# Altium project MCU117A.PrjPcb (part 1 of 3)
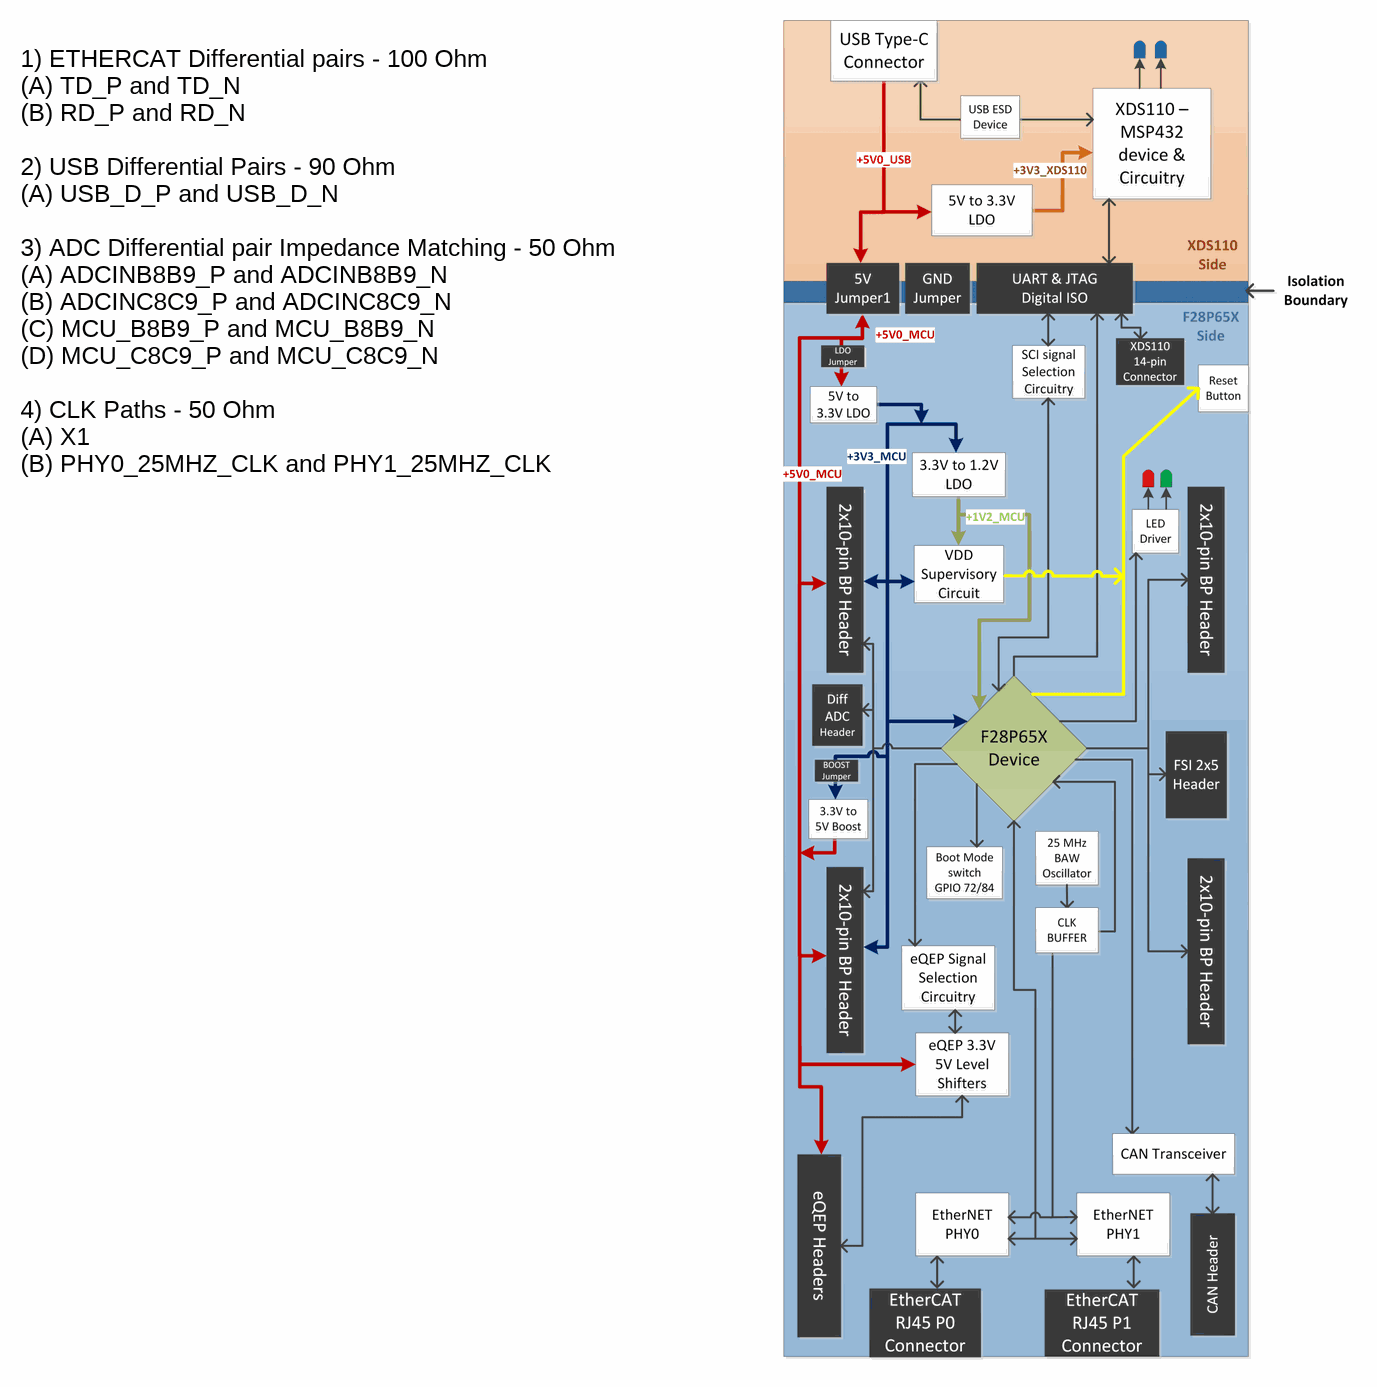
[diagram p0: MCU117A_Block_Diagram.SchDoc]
CopyrightYear: 2023; DrawnBy: Peter Luong; EVM_orderable: LAUNCHXL-F28P65X; PCB_Layout: a0488298; PCB_Rev: A; PRJ_Customer: Public Release; PRJ_Engineer: Peter Luong; PRJ_Number: MCU117; PRJ_Title: LAUNCHXL-F28P65X; SCH_Rev: A; TechSupport: http://www.ti.com/support; TID: N/A
9 sheets, 425 parts. Net scope: global (net labels, ports and power ports of the same name join across sheets).
Board file: MCU117A.PcbDoc
Sheets:
  MCU117A_Block_Diagram.SchDoc
  MCU117A_Connectors.SchDoc
  MCU117A_AltRouting_Misc.SchDoc
  MCU117A_F28P65X_Device.SchDoc
  MCU117A_ADC.SchDoc
  MCU117A_EtherCAT.SchDoc
  MCU117A_USB_and_Power.SchDoc
  MCU117A_XDS110_MCU.SchDoc
  MCU117A_Hardware.SchDoc

## Sheet MCU117A_Block_Diagram.SchDoc
size 431 x 279 mm; Date: Not shown in title block; ApprovedBy: Not shown in title block; CheckedBy: Not shown in title block; Author: Not shown in title block; CompanyName: Not shown in title block; Engineer: Not shown in title block; Organization: Not shown in title block; Address1: Not shown in title block; Address2: Not shown in title block; Address3: Not shown in title block; Address4: Not shown in title block; DocumentNumber: 1; Revision: Use project parameter SCH_Rev; SheetNumber: 1; SheetTotal: 9; PageSetup: Record=PageOptions¦CenterHorizontal=True¦CenterVertical=True¦PrintScale=1.00¦XCorrection=1.00¦YCorrection=1.00¦PrintKind=0¦BorderSize=5000000¦LeftOffset=0¦BottomOffset=0¦Orientation=2¦PaperLength=1000¦PaperWidth=1000¦Scale=100¦PaperSource=15¦PrintQuality=600¦MediaType=1¦DitherType=10¦PaperKind=Letter¦PrintScaleMode=1

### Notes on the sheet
- 1) ETHERCAT Differential pairs - 100 Ohm
  (A) TD_P and TD_N
  (B) RD_P and RD_N
  2) USB Differential Pairs - 90 Ohm
  (A) USB_D_P and USB_D_N
  3) ADC Differential pair Impedance Matching - 50 Ohm
  (A) ADCINB8B9_P and ADCINB8B9_N
  (B) ADCINC8C9_P and ADCINC8C9_N
  (C) MCU_B8B9_P and MCU_B8B9_N
  (D) MCU_C8C9_P and MCU_C8C9_N
  4) CLK Paths - 50 Ohm
  (A) X1
  (B) PHY0_25MHZ_CLK and PHY1_25MHZ_CLK

## Sheet MCU117A_Connectors.SchDoc
size 431 x 279 mm; Date: Not shown in title block; ApprovedBy: Not shown in title block; CheckedBy: Not shown in title block; Author: Not shown in title block; CompanyName: Not shown in title block; Engineer: Not shown in title block; Organization: Not shown in title block; Address1: Not shown in title block; Address2: Not shown in title block; Address3: Not shown in title block; Address4: Not shown in title block; DocumentNumber: 2; Revision: Use project parameter SCH_Rev; SheetNumber: 2; SheetTotal: 9; PageSetup: Record=PageOptions¦CenterHorizontal=True¦CenterVertical=True¦PrintScale=1.00¦XCorrection=1.00¦YCorrection=1.00¦PrintKind=0¦BorderSize=5000000¦LeftOffset=0¦BottomOffset=0¦Orientation=2¦PaperLength=1000¦PaperWidth=1000¦Scale=100¦PaperSource=15¦PrintQuality=600¦MediaType=1¦DitherType=10¦PaperKind=Letter¦PrintScaleMode=1
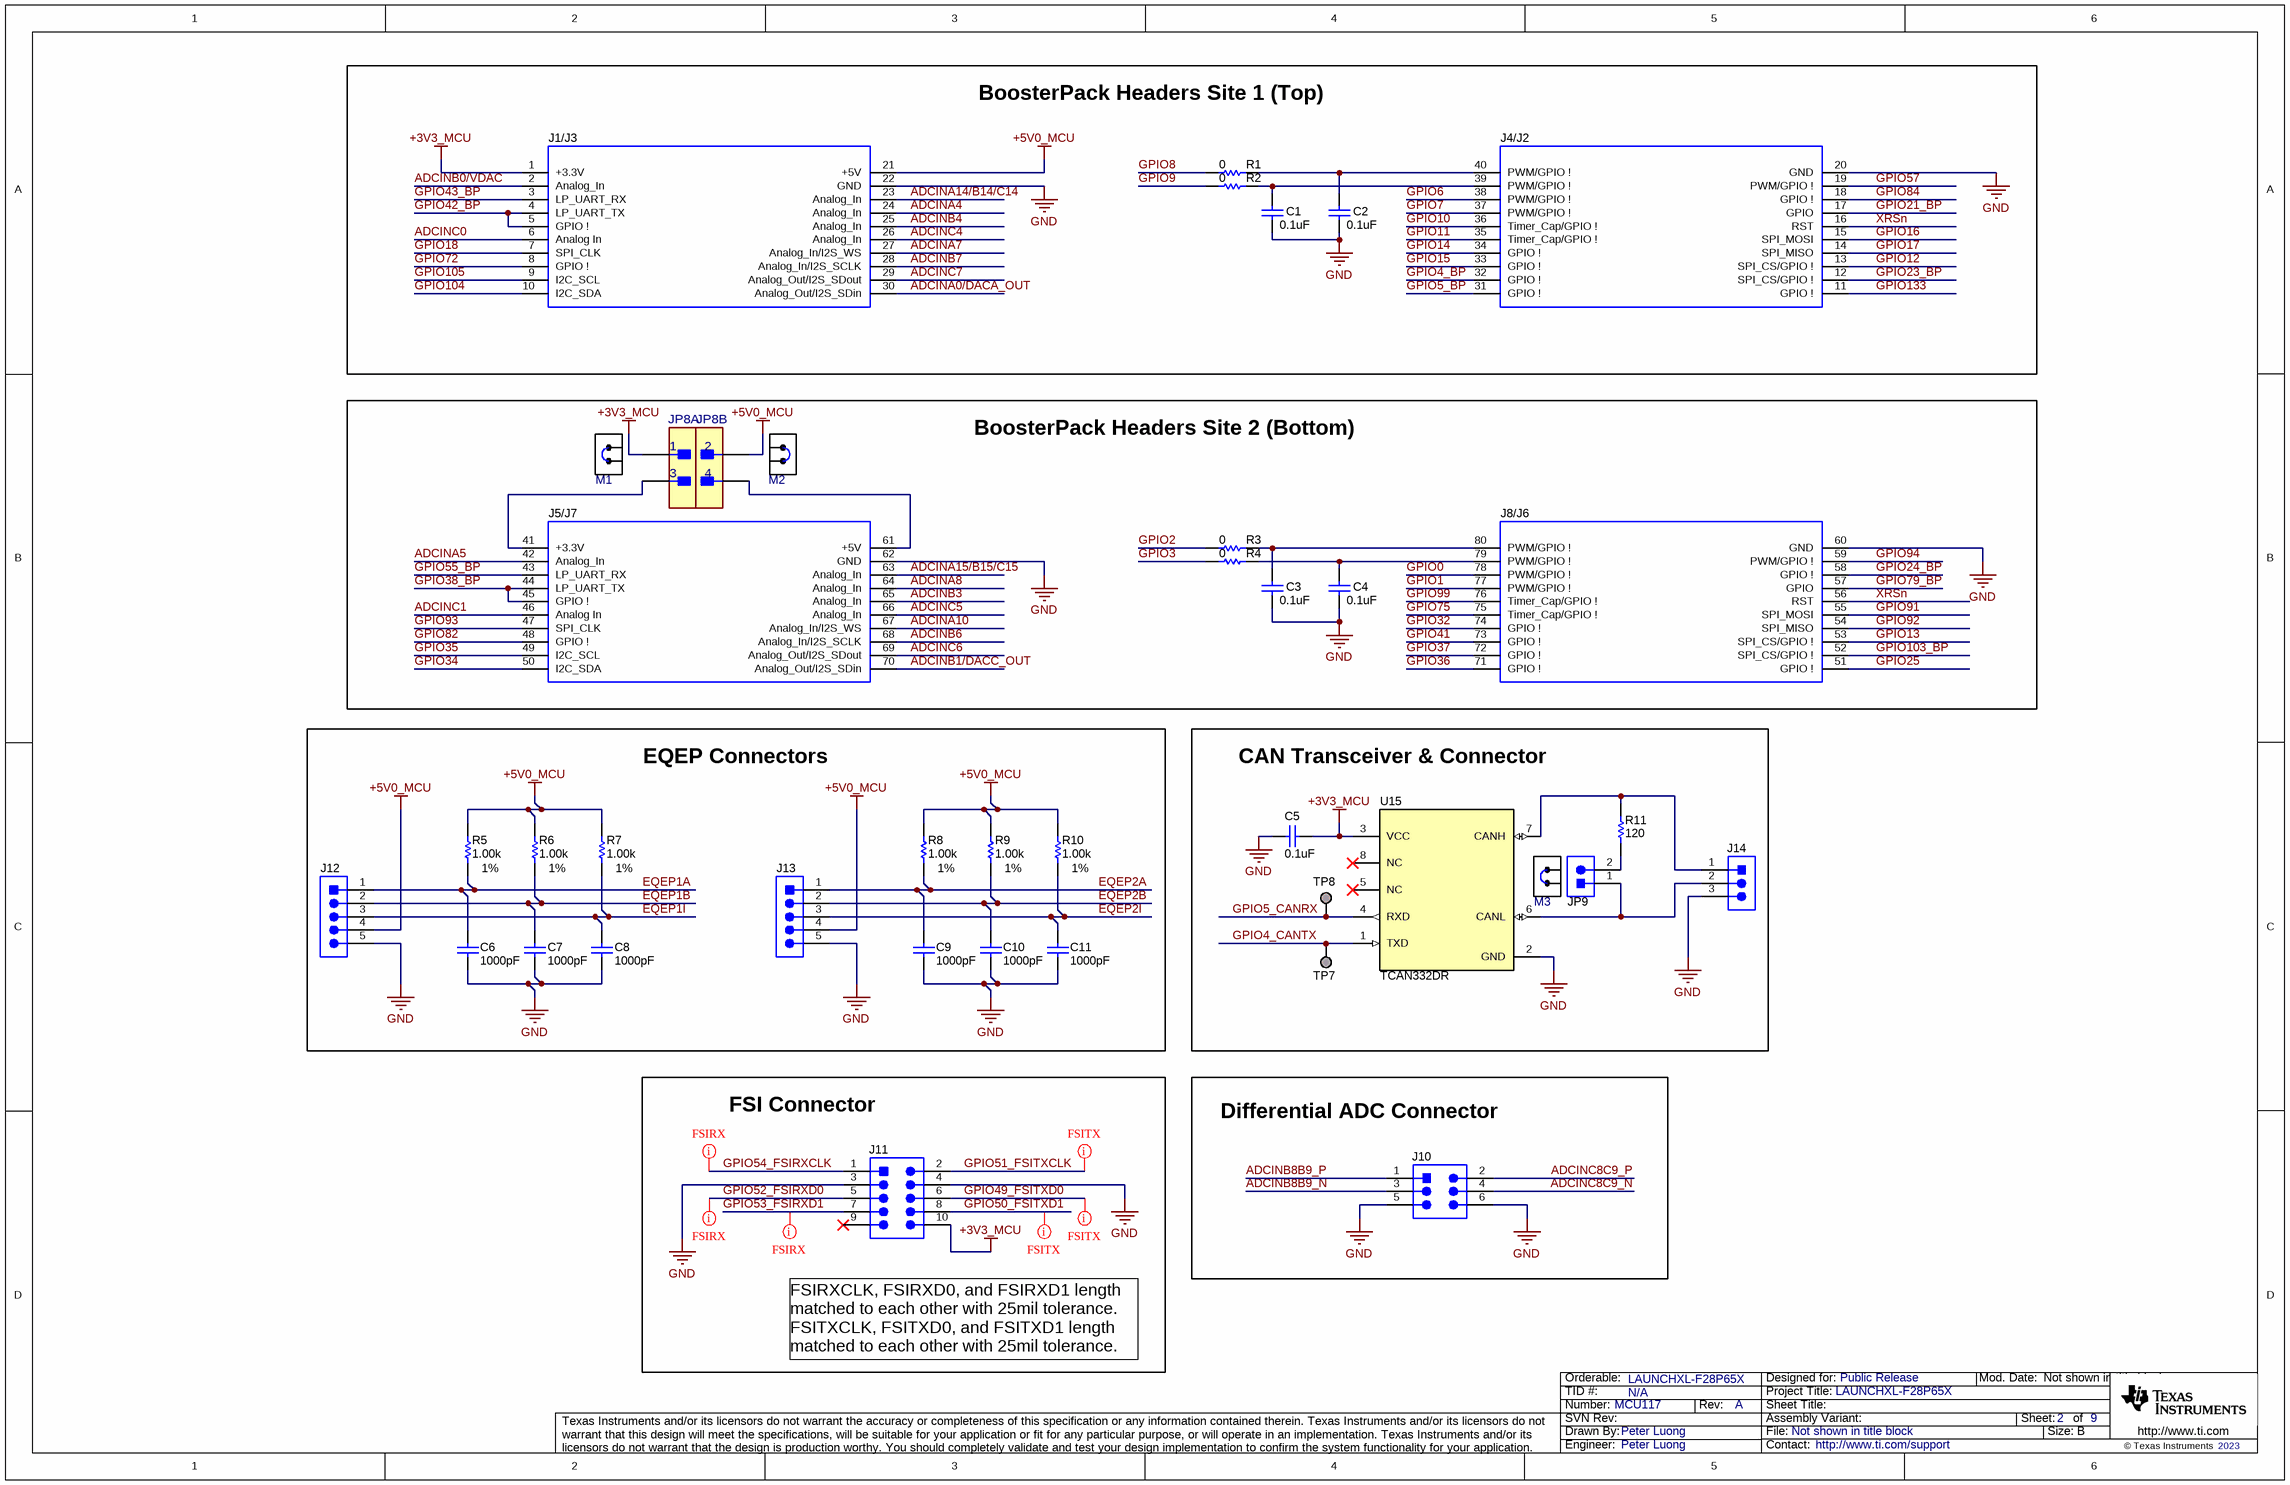
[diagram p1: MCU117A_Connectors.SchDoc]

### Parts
C1  ValueDisplayed: 0.1uF  [0402]  (hidden comment: 885012205037)
C2  ValueDisplayed: 0.1uF  [0402]  (hidden comment: 885012205037)
C3  ValueDisplayed: 0.1uF  [0402]  (hidden comment: 885012205037)
C4  ValueDisplayed: 0.1uF  [0402]  (hidden comment: 885012205037)
C5  ValueDisplayed: 0.1uF  [0402]  (hidden comment: 885012205037)
C6  ValueDisplayed: 1000pF  [0402]  (hidden comment: 885012205061)
C7  ValueDisplayed: 1000pF  [0402]  (hidden comment: 885012205061)
C8  ValueDisplayed: 1000pF  [0402]  (hidden comment: 885012205061)
C9  ValueDisplayed: 1000pF  [0402]  (hidden comment: 885012205061)
C10  ValueDisplayed: 1000pF  [0402]  (hidden comment: 885012205061)
C11  ValueDisplayed: 1000pF  [0402]  (hidden comment: 885012205061)
J1/J3  SSQ-110-03-T-D  [BoosterPack_40pin_J1J3]  (value not drawn)
J4/J2  SSQ-110-03-T-D  [BoosterPack_40pin_J2J4]  (value not drawn)
J5/J7  SSQ-110-03-T-D  [BoosterPack_40pin_J5J7]  (value not drawn)
J8/J6  SSQ-110-03-T-D  [BoosterPack_40pin_J6J8]  (value not drawn)
J10  61300621121  [Wurth_61300621121]  (value not drawn)
J11  61301021121  [WURTH_61301021121]  (value not drawn)
J12  61300511121  [Wurth_61300511121]  (value not drawn)
J13  61300511121  [Wurth_61300511121]  (value not drawn)
J14  61300311121  [WURTH_61300311121]  (value not drawn)
JP8  61300421121  [FP-61300421121_HDR4-MFG]  (value not drawn)  (parts A,B of 2)
JP9  61300211121  [WURTH_61300211121]  (value not drawn)
M1  60900213421  [Wurth_60900213421]  (value not drawn)
M2  60900213421  [Wurth_60900213421]  (value not drawn)
M3  60900213421  [Wurth_60900213421]  (value not drawn)
R1  ValueDisplayed: 0  [0603]  (hidden comment: ERJ-3GEY0R00V)
R2  ValueDisplayed: 0  [0603]  (hidden comment: ERJ-3GEY0R00V)
R3  ValueDisplayed: 0  [0603]  (hidden comment: ERJ-3GEY0R00V)
R4  ValueDisplayed: 0  [0603]  (hidden comment: ERJ-3GEY0R00V)
R5  ValueDisplayed: 1.00k  Value1: 1%  [0402]  (hidden comment: CRCW04021K00FKED)
R6  ValueDisplayed: 1.00k  Value1: 1%  [0402]  (hidden comment: CRCW04021K00FKED)
R7  ValueDisplayed: 1.00k  Value1: 1%  [0402]  (hidden comment: CRCW04021K00FKED)
R8  ValueDisplayed: 1.00k  Value1: 1%  [0402]  (hidden comment: CRCW04021K00FKED)
R9  ValueDisplayed: 1.00k  Value1: 1%  [0402]  (hidden comment: CRCW04021K00FKED)
R10  ValueDisplayed: 1.00k  Value1: 1%  [0402]  (hidden comment: CRCW04021K00FKED)
R11  ValueDisplayed: 120  [0603]  (hidden comment: RC0603FR-07120RL)
TP7  TESTPOINT  [TP_50MIL-25MILHOLE]  (value not drawn)  (no BOM)
TP8  TESTPOINT  [TP_50MIL-25MILHOLE]  (value not drawn)  (no BOM)
U15  TCAN332DR  [D0008A_N]

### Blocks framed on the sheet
BoosterPack Headers Site 1 (Top): C1 C2 J1/J3 J4/J2 R1 R2
BoosterPack Headers Site 2 (Bottom): C3 C4 J5/J7 J8/J6 JP8 M1 M2 R3 R4
EQEP Connectors: C6-C11 J12 J13 R5-R10
CAN Transceiver & Connector: C5 J14 JP9 M3 R11 TP7 TP8 U15
FSI Connector: J11
Differential ADC Connector: J10

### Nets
+3V3_MCU: C5.2 J1/J3.1(+3.3V) J11.10 JP8.1 U15.3(VCC)
+5V0_MCU: J1/J3.21(+5V) J12.4 J13.4 JP8.2 R5.2 R6.2 R7.2 R8.2 R9.2 R10.2
GND: C1.2 C2.2 C3.2 C4.2 C5.1 C6.2 C7.2 C8.2 C9.2 C10.2 C11.2 J1/J3.22(GND) J4/J2.20(GND) J5/J7.62(GND) J8/J6.60(GND) J10.5 J10.6 J11.3 J11.4 J12.5 J13.5 J14.3 U15.2(GND)
ADCINA0/DACA_OUT: J1/J3.30(Analog_Out/I2S_SDin)
ADCINA4: J1/J3.24(Analog_In)
ADCINA5: J5/J7.42(Analog_In)
ADCINA7: J1/J3.27(Analog_In/I2S_WS)
ADCINA8: J5/J7.64(Analog_In)
ADCINA10: J5/J7.67(Analog_In/I2S_WS)
ADCINA14/B14/C14: J1/J3.23(Analog_In)
ADCINA15/B15/C15: J5/J7.63(Analog_In)
ADCINB0/VDAC: J1/J3.2(Analog_In)
ADCINB1/DACC_OUT: J5/J7.70(Analog_Out/I2S_SDin)
ADCINB3: J5/J7.65(Analog_In)
ADCINB4: J1/J3.25(Analog_In)
ADCINB6: J5/J7.68(Analog_In/I2S_SCLK)
ADCINB7: J1/J3.28(Analog_In/I2S_SCLK)
ADCINB8B9_N: J10.3
ADCINB8B9_P: J10.1
ADCINC0: J1/J3.6(Analog_In)
ADCINC1: J5/J7.46(Analog_In)
ADCINC4: J1/J3.26(Analog_In)
ADCINC5: J5/J7.66(Analog_In)
ADCINC6: J5/J7.69(Analog_Out/I2S_SDout)
ADCINC7: J1/J3.29(Analog_Out/I2S_SDout)
ADCINC8C9_N: J10.4
ADCINC8C9_P: J10.2
EQEP1A: C6.1 J12.1 R5.1
EQEP1B: C7.1 J12.2 R6.1
EQEP1I: C8.1 J12.3 R7.1
EQEP2A: C9.1 J13.1 R8.1
EQEP2B: C10.1 J13.2 R9.1
EQEP2I: C11.1 J13.3 R10.1
GPIO0: J8/J6.78(PWM/GPIO_!)
GPIO1: J8/J6.77(PWM/GPIO_!)
GPIO2: R3.2
GPIO3: R4.2
GPIO4_BP: J4/J2.32(GPIO_!)
GPIO4_CANTX: TP7.1 U15.1(TXD)
GPIO5_BP: J4/J2.31(GPIO_!)
GPIO5_CANRX: TP8.1 U15.4(RXD)
GPIO6: J4/J2.38(PWM/GPIO_!)
GPIO7: J4/J2.37(PWM/GPIO_!)
GPIO8: R1.2
GPIO9: R2.2
GPIO10: J4/J2.36(Timer_Cap/GPIO_!)
GPIO11: J4/J2.35(Timer_Cap/GPIO_!)
GPIO12: J4/J2.13(SPI_CS/GPIO_!)
GPIO13: J8/J6.53(SPI_CS/GPIO_!)
GPIO14: J4/J2.34(GPIO_!)
GPIO15: J4/J2.33(GPIO_!)
GPIO16: J4/J2.15(SPI_MOSI)
GPIO17: J4/J2.14(SPI_MISO)
GPIO18: J1/J3.7(SPI_CLK)
GPIO21_BP: J4/J2.17(GPIO)
GPIO23_BP: J4/J2.12(SPI_CS/GPIO_!)
GPIO24_BP: J8/J6.58(GPIO_!)
GPIO25: J8/J6.51(GPIO_!)
GPIO32: J8/J6.74(GPIO_!)
GPIO34: J5/J7.50(I2C_SDA)
GPIO35: J5/J7.49(I2C_SCL)
GPIO36: J8/J6.71(GPIO_!)
GPIO37: J8/J6.72(GPIO_!)
GPIO38_BP: J5/J7.44(LP_UART_TX) J5/J7.45(GPIO_!)
GPIO41: J8/J6.73(GPIO_!)
GPIO42_BP: J1/J3.4(LP_UART_TX) J1/J3.5(GPIO_!)
GPIO43_BP: J1/J3.3(LP_UART_RX)
GPIO49_FSITXD0: J11.6
GPIO50_FSITXD1: J11.8
GPIO51_FSITXCLK: J11.2
GPIO52_FSIRXD0: J11.5
GPIO53_FSIRXD1: J11.7
GPIO54_FSIRXCLK: J11.1
GPIO55_BP: J5/J7.43(LP_UART_RX)
GPIO57: J4/J2.19(PWM/GPIO_!)
GPIO72: J1/J3.8(GPIO_!)
GPIO75: J8/J6.75(Timer_Cap/GPIO_!)
GPIO79_BP: J8/J6.57(GPIO)
GPIO82: J5/J7.48(GPIO_!)
GPIO84: J4/J2.18(GPIO_!)
GPIO91: J8/J6.55(SPI_MOSI)
GPIO92: J8/J6.54(SPI_MISO)
GPIO93: J5/J7.47(SPI_CLK)
GPIO94: J8/J6.59(PWM/GPIO_!)
GPIO99: J8/J6.76(Timer_Cap/GPIO_!)
GPIO103_BP: J8/J6.52(SPI_CS/GPIO_!)
GPIO104: J1/J3.10(I2C_SDA)
GPIO105: J1/J3.9(I2C_SCL)
GPIO133: J4/J2.11(GPIO_!)
XRSn: J4/J2.16(RST) J8/J6.56(RST)
NetC1_1: C1.1 J4/J2.39(PWM/GPIO_!) R2.1
NetC2_1: C2.1 J4/J2.40(PWM/GPIO_!) R1.1
NetC3_1: C3.1 J8/J6.80(PWM/GPIO_!) R3.1
NetC4_1: C4.1 J8/J6.79(PWM/GPIO_!) R4.1
NetJ5/J7_41: J5/J7.41(+3.3V) JP8.3
NetJ5/J7_61: J5/J7.61(+5V) JP8.4
NetJ14_1: J14.1 R11.2 U15.7(CANH)
NetJ14_2: J14.2 JP9.1 U15.6(CANL)
NetJP9_2: JP9.2 R11.1

Not connected (* = marked no-connect by the designer): J11 9*; U15 5(NC)* 8(NC)*

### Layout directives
net class FSIRX: GPIO52_FSIRXD0, GPIO53_FSIRXD1, GPIO54_FSIRXCLK
net class FSITX: GPIO49_FSITXD0, GPIO50_FSITXD1, GPIO51_FSITXCLK

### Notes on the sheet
- FSIRXCLK, FSIRXD0, and FSIRXD1 length matched to each other with 25mil tolerance.
  FSITXCLK, FSITXD0, and FSITXD1 length matched to each other with 25mil tolerance.

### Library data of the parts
C1-C5 = CMP-0006228-2: CAP, CERM, 0.1 uF, 16 V, +/- 10%, X7R, 0402; Manufacturer: Wurth Elektronik; TaMin_C: -55°C; Polarized: N; SizeAreaWB_mm2: 3; Value1: Unknown; U/M: EA; Value: 0.1uF; TaMax_C: 125°C; SizeZ_mm: 0.6; SizeX_mm: 1; SizeY_mm: 0.5; Value2: 16V; Cap_F: 100nF; AEC Category: Q200
C6-C11 = CMP-0006231-2: CAP, CERM, 1000 pF, 50 V, +/- 10%, X7R, 0402; Manufacturer: Wurth Elektronik; Polarized: N; Value: 1000pF; U/M: EA; Cap_F: 1nF; Value1: Unknown; VDC_V: 50V; TaMin_C: -55°C; TaMax_C: 125°C; SizeArea_mm2: 0.5; SizeAreaWB_mm2: 3; SizeX_mm: 1; SizeZ_mm: 0.6; AEC Category: Q200
J1/J3 = CMP-0003837-4: Receptacle, 2.54mm, 10x2, Tin, TH; Alternate PartNumber: CRD-081413-A-G; Manufacturer: Samtec; Alternate Manufacturer: Major League Electronics; Note: Booster Pack 40 pin J1 and J3; Green_Lifecycle: Active; Green_REACh: Incomplete
J4/J2 = CMP-0078266-4: Receptacle, 2.54mm, 10x2, Tin, TH; Alternate PartNumber: CRD-081413-A-G; Manufacturer: Samtec; Alternate Manufacturer: Major League Electronics; Note: Booster Pack 40 pin J2 and J4; Green_REACh: Incomplete; Green_Lifecycle: Active
J5/J7 = CMP-0081070-3: Receptacle, 2.54mm, 10x2, Tin, TH; Alternate PartNumber: CRD-081413-A-G; Manufacturer: Samtec; Alternate Manufacturer: Major League Electronics; Note: Booster Pack 40 pin J5 and J7; Green_REACh: Incomplete; Green_Lifecycle: Active
J8/J6 = CMP-0081071-3: Receptacle, 2.54mm, 10x2, Tin, TH; Alternate PartNumber: CRD-081413-A-G; Manufacturer: Samtec; Alternate Manufacturer: Major League Electronics; Note: Booster Pack 40 pin J6 and J8; Green_REACh: Incomplete; Green_Lifecycle: Active
J10 = CMP-0054802-2: Header, 2.54mm, 3x2, Gold, TH; Manufacturer: Wurth Elektronik; Green_Lifecycle: Active; Shrouded: N; Gender: Male; Green_REACh: Passed; Row_Count: 2; RowSpacing_mm: 2.54
J11 = CMP-0054806-3: Header, 2.54 mm, 5x2, Gold, TH; Manufacturer: Wurth Elektronik; Green_Lifecycle: Active; Green_REACh: Passed; Cert_UL: Y; Current_A: 3A; Gender: Male; Pitch_mm: 2.54; Row_Count: 2; Shrouded: N; Voltage_V: 250V
J12 J13 = CMP-0084909-1: Header, 2.54mm, 5x1, Gold, TH; Manufacturer: Wurth Elektronik; Pitch_mm: 2.54; Gender: Male; Row_Count: 1; Shrouded: N; Current_A: 3A; Voltage_V: 250V
J14 = CMP-0054796-1: Header, 2.54 mm, 3x1, Gold, TH; Manufacturer: Wurth Elektronik; Green_Lifecycle: Active; Green_REACh: Passed; CNHeader: TRUE; CT: FALSE
JP8 = CMP-0092422-1: THT Vertical Pin Header WR-PHD, Pitch 2.54 mm, Dual Row, 4 pins; Manufacturer: Wurth Electronics; DUT-Pitch_mm: 2.54mm; SizeZ_mm: 8.89mm; Voltage_V: 250V; Conn Gender: Male; AEC Qualified: No; Row_Count: 2; ContactFinish: Gold; Conn Orientation: Straight; Current_A: 3A
JP9 = CMP-0054794-1: Header, 2.54 mm, 2x1, Gold, TH; Manufacturer: Wurth Elektronik; Green_Lifecycle: Active; Green_REACh: Passed; CNHeader: TRUE; CT: FALSE
M1-M3 = CMP-0003761-2: Shunt, 2.54mm, Gold, Black; Manufacturer: Wurth Elektronik
R1-R4 = CMP-0025874-4: RES, 0, 5%, 0.1 W, AEC-Q200 Grade 0, 0603; Manufacturer: Panasonic; Power_W: 100mW; TempCo: 600 ppm/C; Value_Code: 0000; Value: 0; EIA_Code: E24; SizeX_mm: 1.6; SizeY_mm: 0.8; SizeZ_mm: 1; Value2: 0.1W; SizeArea_mm2: 1.28; AEC Qualified: Y; VDC_V: 50V; AEC Category: Q200; SizeAreaWB_mm2: 4.68
R5-R10 = CMP-0026071-3: RES, 1.00 k, 1%, 0.063 W, AEC-Q200 Grade 0, 0402; Manufacturer: Vishay-Dale; Value: 1.00k; Res_ohm: 1k; Value_Code: 1k00; Power_W: 63mW; Value2: 0.063W; VDC_V: 50V; TempCo: 100 ppm/C; SizeArea_mm2: 0.5; SizeX_mm: 1; SizeZ_mm: 0.6; EIA_Code: E96; AEC Category: Q200; AEC Qualified: Y; AEC Grade: 0
R11 = CMP-0022769-3: RES, 120, 1%, 0.1 W, 0603; Manufacturer: Yageo America; Value: 120; Value_Code: 120R; Power_W: 100mW; Value2: 0.1W; VDC_V: 150V; TempCo: 200 ppm/C; SizeArea_mm2: 1.28; SizeX_mm: 1.6; SizeY_mm: 0.8; SizeZ_mm: 1; U/M: EA; AEC Category: Q200
TP7 TP8 = CMP-0078143-3: TEST POINT.  No entry in BOM.
U15 = CMP-0080974-2: 3.3-V CAN Transceivers, D0008A (SOIC-8); Alternate Manufacturer: Texas Instruments; SizeAreaWB_mm2: 56.58; SizeZ_mm: 1.75; SizeX_mm: 4.9; SizeY_mm: 6.2; SizeArea_mm2: 30.38; CompType: IC; AEC Qualified: N; AEC Category: Q200

## Sheet MCU117A_AltRouting_Misc.SchDoc
size 431 x 279 mm; Date: Not shown in title block; ApprovedBy: Not shown in title block; CheckedBy: Not shown in title block; Author: Not shown in title block; CompanyName: Not shown in title block; Engineer: Not shown in title block; Organization: Not shown in title block; Address1: Not shown in title block; Address2: Not shown in title block; Address3: Not shown in title block; Address4: Not shown in title block; DocumentNumber: 3; Revision: Use project parameter SCH_Rev; SheetNumber: 3; SheetTotal: 9; PageSetup: Record=PageOptions¦CenterHorizontal=True¦CenterVertical=True¦PrintScale=1.00¦XCorrection=1.00¦YCorrection=1.00¦PrintKind=0¦BorderSize=5000000¦LeftOffset=0¦BottomOffset=0¦Orientation=2¦PaperLength=1000¦PaperWidth=1000¦Scale=100¦PaperSource=15¦PrintQuality=600¦MediaType=1¦DitherType=10¦PaperKind=Letter¦PrintScaleMode=1
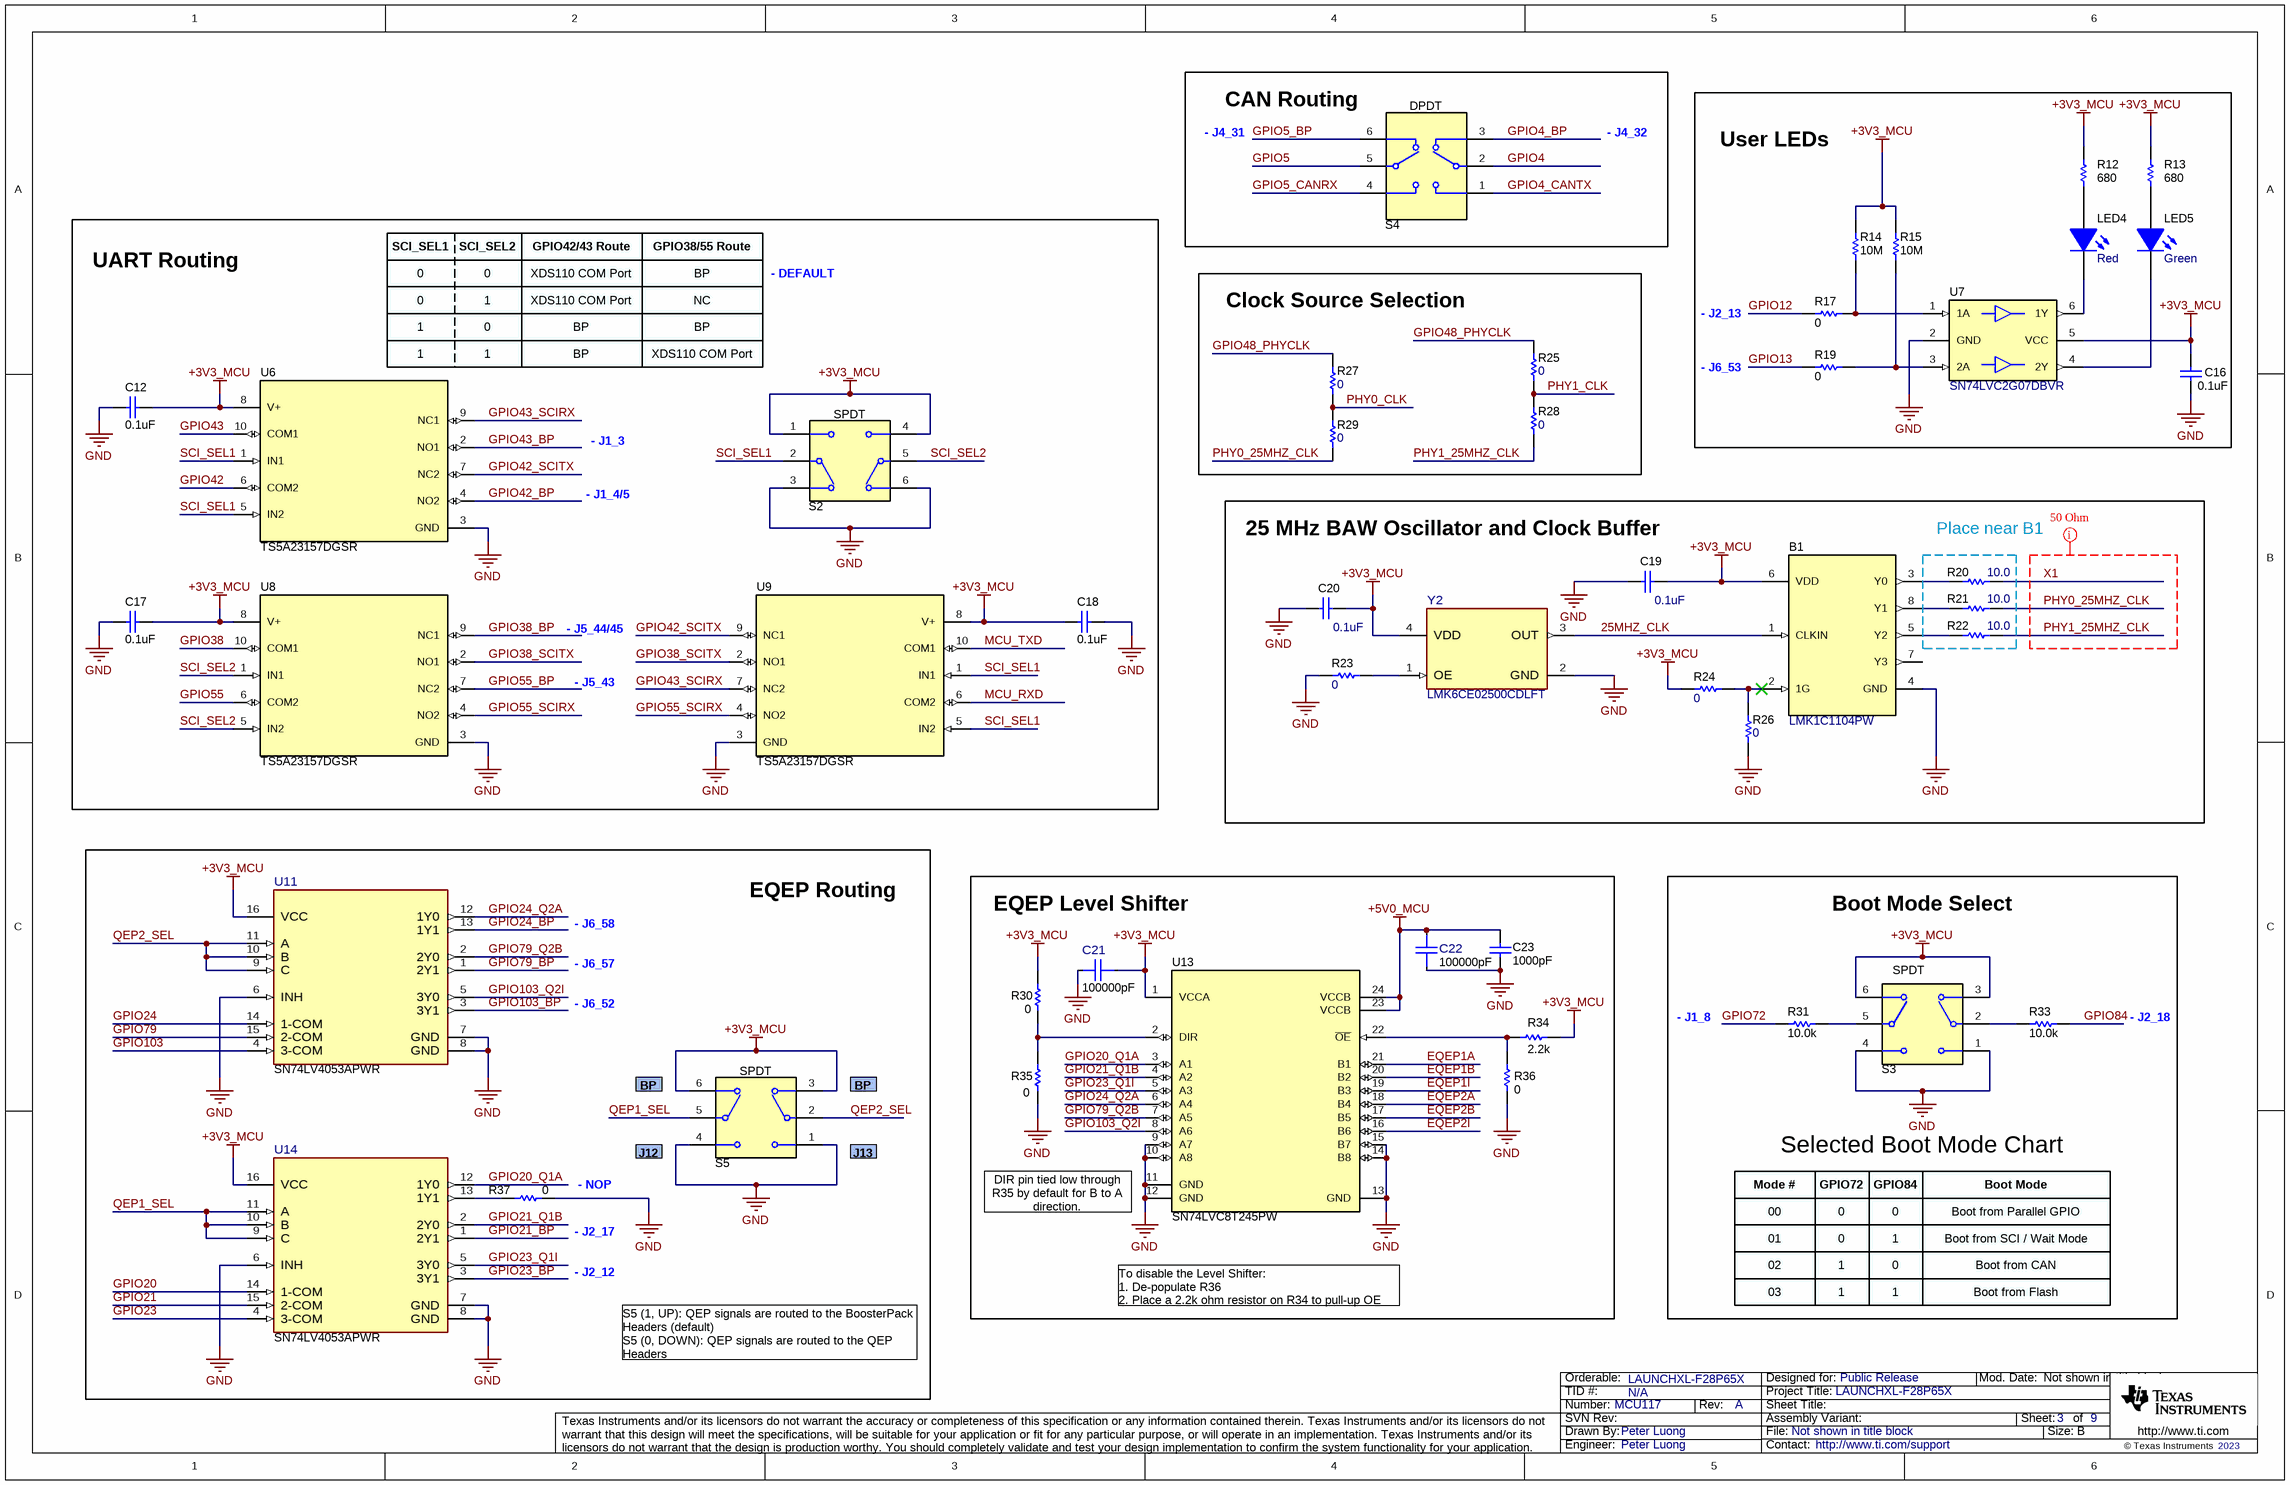
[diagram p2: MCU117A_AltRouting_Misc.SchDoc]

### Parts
B1  LMK1C1104PW  [PW0008A_N]
C12  ValueDisplayed: 0.1uF  [0402]  (hidden comment: 885012205037)
C16  ValueDisplayed: 0.1uF  [0402]  (hidden comment: 885012205037)
C17  ValueDisplayed: 0.1uF  [0402]  (hidden comment: 885012205037)
C18  ValueDisplayed: 0.1uF  [0402]  (hidden comment: 885012205037)
C19  ValueDisplayed: 0.1uF  [0402]  (hidden comment: 885012205037)
C20  ValueDisplayed: 0.1uF  [0402]  (hidden comment: 885012205037)
C21  ValueDisplayed: 100000pF  [FP-885012205018_0402-MFG]  (hidden comment: 885012205018)
C22  ValueDisplayed: 100000pF  [FP-885012205018_0402-MFG]  (hidden comment: 885012205018)
C23  ValueDisplayed: 1000pF  [0402]  (hidden comment: 885012205061)
LED4  value Red  [WL-SMCW_RED_0805]  (hidden comment: 150080SS75000)
LED5  value Green  [LED_LTST-C171]  (hidden comment: LTST-C171GKT)
R12  ValueDisplayed: 680  [0402]  (hidden comment: CRCW0402680RJNED)
R13  ValueDisplayed: 680  [0402]  (hidden comment: CRCW0402680RJNED)
R14  ValueDisplayed: 10M  [0402]  (hidden comment: CRCW040210M0JNED)
R15  ValueDisplayed: 10M  [0402]  (hidden comment: CRCW040210M0JNED)
R17  ValueDisplayed: 0  [0603]  (hidden comment: CRCW06030000Z0EA)
R19  ValueDisplayed: 0  [0603]  (hidden comment: CRCW06030000Z0EA)
R20  ValueDisplayed: 10.0  [CPF0402]  (hidden comment: CPF0402B10RE1)
R21  ValueDisplayed: 10.0  [CPF0402]  (hidden comment: CPF0402B10RE1)
R22  ValueDisplayed: 10.0  [CPF0402]  (hidden comment: CPF0402B10RE1)
R23  ValueDisplayed: 0  [0402]  (hidden comment: CRCW04020000Z0EDHP)
R24  ValueDisplayed: 0  [0402]  (hidden comment: CRCW04020000Z0EDHP)
R25  ValueDisplayed: 0  [0603]  (hidden comment: ERJ-3GEY0R00V)
R26  ValueDisplayed: 0  [0402]  (hidden comment: CRCW04020000Z0EDHP)
R27  ValueDisplayed: 0  [0603]  (hidden comment: ERJ-3GEY0R00V)
R28  ValueDisplayed: 0  [0603]  (hidden comment: ERJ-3GEY0R00V)
R29  ValueDisplayed: 0  [0603]  (hidden comment: ERJ-3GEY0R00V)
R30  ValueDisplayed: 0  [0603]  (hidden comment: CRCW06030000Z0EA)
R31  ValueDisplayed: 10.0k  [0603]  (hidden comment: RC0603FR-0710KL)
R33  ValueDisplayed: 10.0k  [0603]  (hidden comment: RC0603FR-0710KL)
R34  ValueDisplayed: 2.2k  [0603]  (hidden comment: CRCW06032K20JNEA)
R35  ValueDisplayed: 0  [0603]  (hidden comment: CRCW06030000Z0EA)
R36  ValueDisplayed: 0  [0603]  (hidden comment: CRCW06030000Z0EA)
R37  ValueDisplayed: 0  [0603]  (hidden comment: CRCW06030000Z0EA)
S2  CAS-D20TA  [SW_CAS-D20TA]  (value not drawn)
S3  CAS-D20TA  [SW_CAS-D20TA]  (value not drawn)
S4  CAS-220TA  [SW_CAS-220TA]  (value not drawn)
S5  CAS-D20TA  [SW_CAS-D20TA]  (value not drawn)
U6  TS5A23157DGSR  [DGS0010A_N]
U7  SN74LVC2G07DBVR  [DBV0006A_N]
U8  TS5A23157DGSR  [DGS0010A_N]
U9  TS5A23157DGSR  [DGS0010A_N]
U11  SN74LV4053APWR  [PW0016A-MFG]
U13  SN74LVC8T245PW  [PW0024A_N]
U14  SN74LV4053APWR  [PW0016A-MFG]
Y2  LMK6CE02500CDLFT  [DLF0004A-MFG]

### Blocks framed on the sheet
CAN Routing: S4
User LEDs: C16 LED4 LED5 R12-R15 R17 R19 U7
UART Routing: C12 C17 C18 S2 U6 U8 U9
Clock Source Selection: R25 R27-R29
25 MHz BAW Oscillator and Clock Buffer: B1 C19 C20 R20-R24 R26 Y2
EQEP Routing: R37 S5 U11 U14
EQEP Level Shifter: C21-C23 R30 R34-R36 U13
Selected Boot Mode Chart: R31 R33 S3

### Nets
+3V3_MCU: B1.6(VDD) C12.2 C16.1 C17.2 C18.1 C19.1 C20.1 C21.1 R12.2 R13.2 R14.2 R15.2 R24.1 R30.2 R34.2 S2.1 S2.4 S3.3 S3.6 S5.3 S5.6 U6.8(V+) U7.5(VCC) U8.8(V+) U9.8(V+) U11.16(VCC) U13.1(VCCA) U14.16(VCC) Y2.4(VDD)
+5V0_MCU: C22.2 C23.1 U13.23(VCCB) U13.24(VCCB)
GND: B1.4(GND) C12.1 C16.2 C17.1 C18.2 C19.2 C20.2 C21.2 C22.1 C23.2 R23.1 R26.1 R35.1 R36.2 R37.2 S2.3 S2.6 S3.1 S3.4 S5.1 S5.4 U6.3(GND) U7.2(GND) U8.3(GND) U9.3(GND) U11.6(INH) U11.7(GND) U11.8(GND) U13.9(A7) U13.10(A8) U13.11(GND) U13.12(GND) U13.13(GND) U13.14(B8) U13.15(B7) U14.6(INH) U14.7(GND) U14.8(GND) Y2.2(GND)
25MHZ_CLK: B1.1(CLKIN) Y2.3(OUT)
EQEP1A: U13.21(B1)
EQEP1B: U13.20(B2)
EQEP1I: U13.19(B3)
EQEP2A: U13.18(B4)
EQEP2B: U13.17(B5)
EQEP2I: U13.16(B6)
GPIO4: S4.2
GPIO4_BP: S4.3
GPIO4_CANTX: S4.1
GPIO5: S4.5
GPIO5_BP: S4.6
GPIO5_CANRX: S4.4
GPIO12: R17.1
GPIO13: R19.1
GPIO20: U14.14(1-COM)
GPIO20_Q1A: U13.3(A1) U14.12(1Y0)
GPIO21: U14.15(2-COM)
GPIO21_BP: U14.1(2Y1)
GPIO21_Q1B: U13.4(A2) U14.2(2Y0)
GPIO23: U14.4(3-COM)
GPIO23_BP: U14.3(3Y1)
GPIO23_Q1I: U13.5(A3) U14.5(3Y0)
GPIO24: U11.14(1-COM)
GPIO24_BP: U11.13(1Y1)
GPIO24_Q2A: U11.12(1Y0) U13.6(A4)
GPIO38: U8.10(COM1)
GPIO38_BP: U8.9(NC1)
GPIO38_SCITX: U8.2(NO1) U9.2(NO1)
GPIO42: U6.6(COM2)
GPIO42_BP: U6.4(NO2)
GPIO42_SCITX: U6.7(NC2) U9.9(NC1)
GPIO43: U6.10(COM1)
GPIO43_BP: U6.2(NO1)
GPIO43_SCIRX: U6.9(NC1) U9.7(NC2)
GPIO48_PHYCLK: R25.1 R27.1
GPIO55: U8.6(COM2)
GPIO55_BP: U8.7(NC2)
GPIO55_SCIRX: U8.4(NO2) U9.4(NO2)
GPIO72: R31.1
GPIO79: U11.15(2-COM)
GPIO79_BP: U11.1(2Y1)
GPIO79_Q2B: U11.2(2Y0) U13.7(A5)
GPIO84: R33.2
GPIO103: U11.4(3-COM)
GPIO103_BP: U11.3(3Y1)
GPIO103_Q2I: U11.5(3Y0) U13.8(A6)
MCU_RXD: U9.6(COM2)
MCU_TXD: U9.10(COM1)
PHY0_25MHZ_CLK: R21.2 R29.2
PHY0_CLK: R27.2 R29.1
PHY1_25MHZ_CLK: R22.2 R28.2
PHY1_CLK: R25.2 R28.1
QEP1_SEL: S5.5(C) U14.9(C) U14.10(B) U14.11(A)
QEP2_SEL: S5.2(C) U11.9(C) U11.10(B) U11.11(A)
SCI_SEL1: S2.2(C) U6.1(IN1) U6.5(IN2) U9.1(IN1) U9.5(IN2)
SCI_SEL2: S2.5(C) U8.1(IN1) U8.5(IN2)
X1: R20.2
NetB1_2: B1.2(1G) R24.2 R26.2
NetB1_3: B1.3(Y0) R20.1
NetB1_5: B1.5(Y2) R22.1
NetB1_8: B1.8(Y1) R21.1
NetLED4_1: LED4.1(K) U7.6(1Y)
NetLED4_2: LED4.2(A) R12.1
NetLED5_1: LED5.1(A) R13.1
NetLED5_2: LED5.2(K) U7.4(2Y)
NetR14_1: R14.1 R17.2 U7.1(1A)
NetR15_1: R15.1 R19.2 U7.3(2A)
NetR23_2: R23.2 Y2.1(OE)
NetR30_1: R30.1 R35.2 U13.2(DIR)
NetR31_2: R31.2 S3.5(C)
NetR33_1: R33.1 S3.2(C)
NetR34_1: R34.1 R36.1 U13.22(~{OE})
NetR37_1: R37.1 U14.13(1Y1)

Not connected (* = marked no-connect by the designer): B1 7(Y3)

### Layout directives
50 Ohm Impedance: Undefined: PHY0_25MHZ_CLK, PHY1_25MHZ_CLK, X1

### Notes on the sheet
- - J4_31
- (near S4) DPDT
- - J4_32
- SCI_SEL1
- 0
- SCI_SEL2
- 1
- GPIO42/43 Route
- XDS110 COM Port
- GPIO38/55 Route
- BP
- NC
- - DEFAULT
- (near U6) 1
- - J2_13
- - J6_53
- - J1_3
- (near S2) SPDT
- - J1_4/5
- Place near B1
- - J5_44/45
- - J5_43
- Boot Mode Select
- - J6_58
- - J6_57
- (near S3) SPDT
- - J6_52
- - J1_8
- - J2_18
- (near S5) SPDT
- J12
- J13
- (near R37) - NOP
- (near R37) - J2_17
- (near U13) DIR pin tied low through R35 by default for B to A direction.
- Mode #
- 00
- 01
- GPIO72
- GPIO84
- Boot Mode
- Boot from Parallel GPIO
- Boot from SCI / Wait Mode
- - J2_12
- To disable the Level Shifter:
  1. De-populate R36
  2. Place a 2.2k ohm resistor on R34 to pull-up OE
- 02
- 03
- Boot from CAN
- Boot from Flash
- S5 (1, UP): QEP signals are routed to the BoosterPack Headers (default)
  S5 (0, DOWN): QEP signals are routed to the QEP Headers

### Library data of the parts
B1 = CMP-0860874-2: 3.3-V and 2.5-V LVCMOS High-Performance Clock Buffer Family, PW0008A (TSSOP-8); Alternate PartNumber: LMK1C1104PWR; Manufacturer: Texas Instruments; AEC Qualified: N; SizeZ_mm: 1.2; SizeY_mm: 3; SizeArea_mm2: 19.2; CompType: IC; SizeX_mm: 6.4; SizeAreaWB_mm2: 42; AEC Category: Q200
C12 C16-C20 = CMP-0006228-2: as C1 on sheet MCU117A_Connectors
C21 C22 = CMP-0090362-1: 0.1µF ±10% 10V Ceramic Capacitor X7R 0402 (1005 Metric); Manufacturer: Wurth Electronics; AEC Qualified: No; Value: 100nF; SizeZ_mm: 0.55mm; TempCo: 15%
C23 = CMP-0006231-2: as C6 on sheet MCU117A_Connectors
LED4 = CMP-0002951-3: LED, Red, SMD; Manufacturer: Wurth Elektronik; Type: AlInGaP; Vf_V: 1.9V; Io_A: 30mA; Vr_V: 5V; Ir_A: 25µA; Tjmax_C: 85°C; Power_TotalModule: 72mW; Value1: 0.072W; Angle: 140
LED5 = CMP-0002830-3: LED, Green, SMD; Manufacturer: Lite-On; Type: AlInGaP; Vf_V: 2.1V; Io_A: 20A; Value1: W; SizeAreaWB_mm2: 6.75; SizeArea_mm2: 2.5; SizeX_mm: 2; SizeY_mm: 1.25; SizeZ_mm: 1.2
R12 R13 = CMP-0026962-3: RES, 680, 5%, 0.063 W, AEC-Q200 Grade 0, 0402; Manufacturer: Vishay-Dale; Power_W: 63mW; TempCo: 200 ppm/C; Value_Code: 680R; Value: 680; EIA_Code: E24; SizeX_mm: 1; SizeY_mm: 0.5; SizeZ_mm: 0.6; Value2: 0.063W; AEC Qualified: Y; VDC_V: 50V; AEC Category: Q200; AEC Grade: 0
R14 R15 = CMP-0026826-2: RES, 10 M, 5%, 0.063 W, AEC-Q200 Grade 0, 0402; Manufacturer: Vishay-Dale; Value: 10Meg; Value_Code: 10M0; Power_W: 63mW; Value2: 0.063W; VDC_V: 50V; TempCo: 200 ppm/C; SizeArea_mm2: 0.5; SizeX_mm: 1; SizeZ_mm: 0.6; EIA_Code: E24; AEC Category: Q200; AEC Qualified: Y; AEC Grade: 0
R17 R19 R30 R35-R37 = CMP-0025697-4: RES, 0, 5%, 0.1 W, AEC-Q200 Grade 0, 0603; Manufacturer: Vishay-Dale; Value: 0; Value_Code: 0000; Power_W: 100mW; Value2: 0.1W; VDC_V: 75V; TempCo: 200 ppm/C; SizeArea_mm2: 1.28; SizeX_mm: 1.6; SizeY_mm: 0.8; SizeZ_mm: 1; EIA_Code: E24; AEC Category: Q200; AEC Qualified: Y
R20-R22 = CMP-0026765-1: RES, 10.0, 0.1%, 0.063 W, 0402; Manufacturer: TE Connectivity; Power_W: 63mW; TempCo: 25 ppm/C; Value_Code: 10R0; U/M: EA; Value: 10.0; EIA_Code: E192; Res_ohm: 10; SizeX_mm: 1; SizeY_mm: 0.5; SizeZ_mm: 0.35; Value2: 0.063W; AEC Qualified: N; AEC Category: Q200
R23 R24 R26 = CMP-0081856-1: RES, 0, 0%, 0.2 W, AEC-Q200 Grade 0, 0402; Manufacturer: Vishay-Dale; SizeAreaWB_mm2: 3; SizeArea_mm2: 0.5; AEC Qualified: Y; AEC Category: Q200; Value: 0; SizeZ_mm: 0.6; Power_W: 200mW; VDC_V: 50V; Value2: 0.2W; SizeX_mm: 1
R25 R27-R29 = CMP-0025874-4: as R1 on sheet MCU117A_Connectors
R31 R33 = CMP-0022746-5: RES, 10.0 k, 1%, 0.1 W, 0603; Manufacturer: Yageo; Power_W: 100mW; TempCo: 100 ppm/C; Value_Code: 10k0; Value: 10.0k; EIA_Code: E96; Res_ohm: 10k; SizeX_mm: 1.6; SizeY_mm: 0.8; SizeZ_mm: 1; Value2: 0.1W; SizeArea_mm2: 1.28; AEC Qualified: N; VDC_V: 75V; AEC Category: Q200; SizeAreaWB_mm2: 4.68
R34 = CMP-0025769-4: RES, 2.2 k, 5%, 0.1 W, AEC-Q200 Grade 0, 0603; Manufacturer: Vishay-Dale; Value: 2.2k; Value_Code: 2k20; Power_W: 100mW; Value2: 0.1W; VDC_V: 75V; TempCo: 200 ppm/C; SizeArea_mm2: 1.28; SizeX_mm: 1.6; SizeY_mm: 0.8; SizeZ_mm: 1; EIA_Code: E24; AEC Category: Q200; AEC Qualified: Y; AEC Grade: 0
S2 S5 = CMP-0002233-1: Switch, Dual SPDT,  2 Pos, 0.1A, 6VDC, SMD; Manufacturer: Copal Electronics; VDC_V: 6V; SwitchFunction: On-On; PositionCount: 2; CurrentRating_mA: 100A
S3 = CMP-0002233-1: Switch, Dual SPDT,  2 Pos, 0.1A, 6VDC, SMD; Manufacturer: Copal Electronics; CurrentRating_mA: 100A; SwitchFunction: On-On; VDC_V: 6V; PositionCount: 2
S4 = CMP-0002123-2: SLIDE SWITCH DPDT  .1A, SMT; Manufacturer: Copal Electronics; VDC_V: 6V; SwitchFunction: On-On; PositionCount: 2; CurrentRating_mA: 100A
U6 U8 U9 = CMP-0067418-1: DUAL 10-Ohm SPDT ANALOG SWITCH, DGS0010A (VSSOP-10); Alternate PartNumber: TS5A23157DGST; Alternate Manufacturer: Texas Instruments; Green_Lifecycle: Active; SizeAreaWB_mm2: 23.6; Green_REACh: Passed; U/M: EA; SizeZ_mm: 1.1; SizeX_mm: 4.9; SizeY_mm: 3.0; SizeArea_mm2: 14.7; CompType: IC
U7 = CMP-0051789-2: Dual Buffer/Driver with Open-Drain Output, DBV0006A, LARGE T&R; Manufacturer: Texas Instruments; VCC(Min)(V): 1.65; VCC(Max)(V): 5.5; Output Type: CMOS; ICC @ Nom Voltage(Max)(mA): 0.01; Input Type: CMOS/TTL; Bits(#): 2; F @ Nom Voltage(Max)(Mhz): 150; Rating: Catalog; Technology Family: LVC; Voltage(Nom)(V): 1.8,2.5,3.3,5; Schmitt Trigger: No; Output Drive (IOL/IOH)(Max)(mA): 32/-32; tpd @ Nom Voltage(Max)(ns): 8.6,4.4,3.7,2.9; Logic: True; Sub-Family: Inverting Buffer/Driver; AEC Category: Q200; AEC Qualified: N; CompType: IC; Green_Lifecycle: Active; Green_REACh: Passed; SizeArea_mm2: 8.12; SizeAreaWB_mm2: 14.82; SizeX_mm: 2.8; SizeY_mm: 2.9; SizeZ_mm: 1.45
U11 U14 = CMP-0089841-1: 3 Circuit IC Switch 2:1 75Ohm 16-TSSOP; Manufacturer: Texas Instruments; TaMax_C: +85°C; Max Supply Voltage: 5.5V; PositionCount: 3; AEC Qualified: No; SizeZ_mm: 1.2mm; Standoff Height: 0.05mm; On State Resistance: 100-225Ω; Min Supply Voltage: 2V; -3Db Bandwith: 50MHz; Nominal Supply Current: 20uA; TaMin_C: -40°C
U13 = CMP-0066458-2: 8-Bit Dual-Supply Bus Transceiver with Configurable Voltage-Level Shifting and Three-State Outputs, PW0024A (TSSOP-24); Alternate Manufacturer: Texas Instruments; SizeAreaWB_mm2: 82.32; SizeZ_mm: 1.2; SizeX_mm: 6.4; SizeY_mm: 7.8; SizeArea_mm2: 49.92; CompType: IC; AEC Category: Q200; AEC Qualified: N; Rating: Catalog
Y2 = CMP-0096024-2: High-Performance BAW Oscillator; Manufacturer: Texas Instruments; Load Capacitance: 30pF; TJmax_C: +125°C; Frequency Stability: 25ppm; SizeZ_mm: 1mm; Max Supply Current: 50mA; Min Supply Voltage: 2.375V; Standoff Height: 0mm; Frequency_Fixed: 25MHz; Max Supply Voltage: 3.465V; TaMax_C: +105°C; AEC Qualified: No; TaMin_C: -40°C; AEC Category: Q200; CompType: IC

## Sheet MCU117A_F28P65X_Device.SchDoc
size 431 x 279 mm; Date: Not shown in title block; ApprovedBy: Not shown in title block; CheckedBy: Not shown in title block; Author: Not shown in title block; CompanyName: Not shown in title block; Engineer: Not shown in title block; Organization: Not shown in title block; Address1: Not shown in title block; Address2: Not shown in title block; Address3: Not shown in title block; Address4: Not shown in title block; DocumentNumber: 4; Revision: Use project parameter SCH_Rev; SheetNumber: 4; SheetTotal: 9; PageSetup: Record=PageOptions¦CenterHorizontal=True¦CenterVertical=True¦PrintScale=1.00¦XCorrection=1.00¦YCorrection=1.00¦PrintKind=0¦BorderSize=5000000¦LeftOffset=0¦BottomOffset=0¦Orientation=2¦PaperLength=1000¦PaperWidth=1000¦Scale=100¦PaperSource=15¦PrintQuality=600¦MediaType=1¦DitherType=10¦PaperKind=Letter¦PrintScaleMode=1
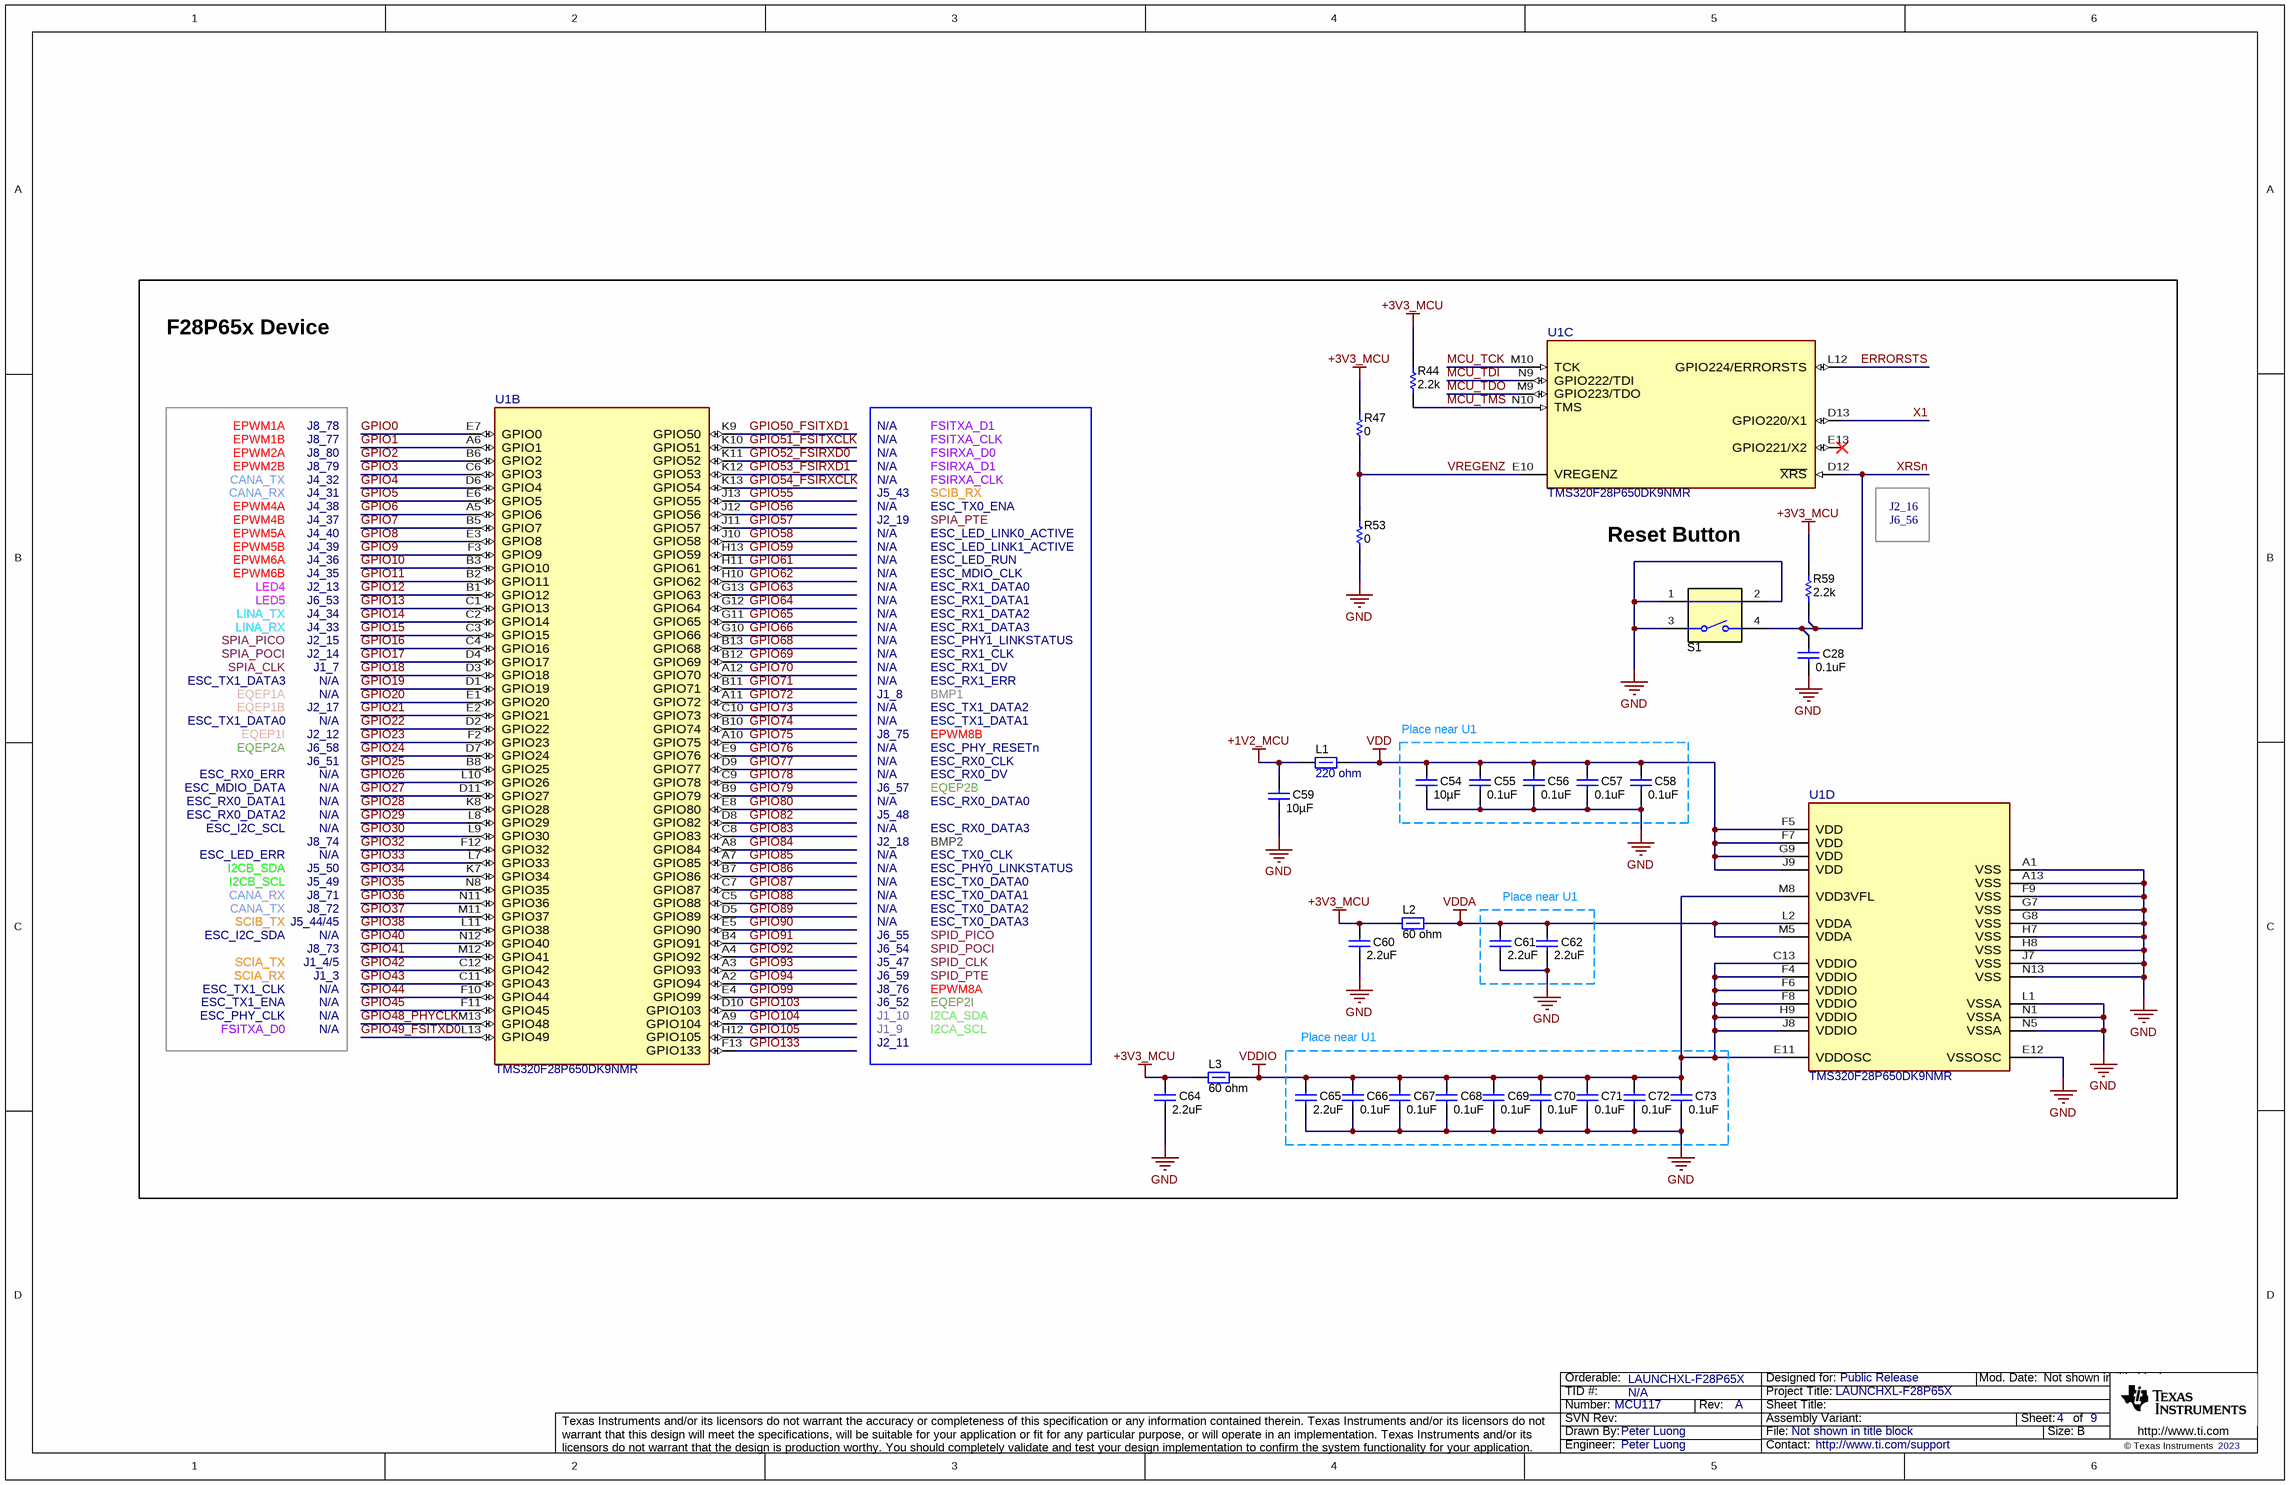
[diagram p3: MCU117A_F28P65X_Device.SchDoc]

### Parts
C28  ValueDisplayed: 0.1uF  [0402]  (hidden comment: 885012205037)
C54  ValueDisplayed: 10µF  [0603]  (hidden comment: GRM188R61C106KAALD)
C55  ValueDisplayed: 0.1uF  [0402]  (hidden comment: 885012205037)
C56  ValueDisplayed: 0.1uF  [0402]  (hidden comment: 885012205037)
C57  ValueDisplayed: 0.1uF  [0402]  (hidden comment: 885012205037)
C58  ValueDisplayed: 0.1uF  [0402]  (hidden comment: 885012205037)
C59  ValueDisplayed: 10µF  [0603]  (hidden comment: GRM188R61C106KAALD)
C60  ValueDisplayed: 2.2uF  [0603]  (hidden comment: 885012106018)
C61  ValueDisplayed: 2.2uF  [0603]  (hidden comment: 885012106018)
C62  ValueDisplayed: 2.2uF  [0603]  (hidden comment: 885012106018)
C64  ValueDisplayed: 2.2uF  [0603]  (hidden comment: 885012106018)
C65  ValueDisplayed: 2.2uF  [0603]  (hidden comment: 885012106018)
C66  ValueDisplayed: 0.1uF  [0402]  (hidden comment: 885012205037)
C67  ValueDisplayed: 0.1uF  [0402]  (hidden comment: 885012205037)
C68  ValueDisplayed: 0.1uF  [0402]  (hidden comment: 885012205037)
C69  ValueDisplayed: 0.1uF  [0402]  (hidden comment: 885012205037)
C70  ValueDisplayed: 0.1uF  [0402]  (hidden comment: 885012205037)
C71  ValueDisplayed: 0.1uF  [0402]  (hidden comment: 885012205037)
C72  ValueDisplayed: 0.1uF  [0402]  (hidden comment: 885012205037)
C73  ValueDisplayed: 0.1uF  [0402]  (hidden comment: 885012205037)
L1  value 220 ohm  [0805_HV]  (hidden comment: BLM21PG221SN1D)
L2  60 ohm  [0805_HV]
L3  60 ohm  [0805_HV]
R44  ValueDisplayed: 2.2k  [0402]  (hidden comment: CRCW04022K20JNED)
R47  ValueDisplayed: 0  [0603]  (hidden comment: ERJ-3GEY0R00V)
R53  ValueDisplayed: 0  [0603]  (hidden comment: ERJ-3GEY0R00V)
R59  ValueDisplayed: 2.2k  [0402]  (hidden comment: CRCW04022K20JNED)
S1  1188E-1K2-V-TR  [SW_1188E]  (value not drawn)
U1  TMS320F28P650DK9NMR  [NMR0169A-MFG]  (parts B,C,D of 4)

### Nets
+1V2_MCU: C59.1 L1.1
+3V3_MCU: C60.1 C64.1 L2.1 L3.1 R44.2 R47.2 R59.2
GND: C28.2 C54.2 C55.2 C56.2 C57.2 C58.2 C59.2 C60.2 C61.2 C62.2 C64.2 C65.2 C66.2 C67.2 C68.2 C69.2 C70.2 C71.2 C72.2 C73.2 R53.1 S1.1 S1.2 S1.3 U1.A1(VSS) U1.A13(VSS) U1.E12(VSSOSC) U1.F9(VSS) U1.G7(VSS) U1.G8(VSS) U1.H7(VSS) U1.H8(VSS) U1.J7(VSS) U1.L1(VSSA) U1.N1(VSSA) U1.N5(VSSA) U1.N13(VSS)
VDD: C54.1 C55.1 C56.1 C57.1 C58.1 L1.2 U1.F5(VDD) U1.F7(VDD) U1.G9(VDD) U1.J9(VDD)
VDDA: C61.1 C62.1 L2.2 U1.L2(VDDA) U1.M5(VDDA)
VDDIO: C65.1 C66.1 C67.1 C68.1 C69.1 C70.1 C71.1 C72.1 C73.1 L3.2 U1.C13(VDDIO) U1.E11(VDDOSC) U1.F4(VDDIO) U1.F6(VDDIO) U1.F8(VDDIO) U1.H9(VDDIO) U1.J8(VDDIO) U1.M8(VDD3VFL)
ERRORSTS: U1.L12(GPIO224/ERRORSTS)
GPIO0: U1.E7(GPIO0)
GPIO1: U1.A6(GPIO1)
GPIO2: U1.B6(GPIO2)
GPIO3: U1.C6(GPIO3)
GPIO4: U1.D6(GPIO4)
GPIO5: U1.E6(GPIO5)
GPIO6: U1.A5(GPIO6)
GPIO7: U1.B5(GPIO7)
GPIO8: U1.E3(GPIO8)
GPIO9: U1.F3(GPIO9)
GPIO10: U1.B3(GPIO10)
GPIO11: U1.B2(GPIO11)
GPIO12: U1.B1(GPIO12)
GPIO13: U1.C1(GPIO13)
GPIO14: U1.C2(GPIO14)
GPIO15: U1.C3(GPIO15)
GPIO16: U1.C4(GPIO16)
GPIO17: U1.D4(GPIO17)
GPIO18: U1.D3(GPIO18)
GPIO19: U1.D1(GPIO19)
GPIO20: U1.E1(GPIO20)
GPIO21: U1.E2(GPIO21)
GPIO22: U1.D2(GPIO22)
GPIO23: U1.F2(GPIO23)
GPIO24: U1.D7(GPIO24)
GPIO25: U1.B8(GPIO25)
GPIO26: U1.L10(GPIO26)
GPIO27: U1.D11(GPIO27)
GPIO28: U1.K8(GPIO28)
GPIO29: U1.L8(GPIO29)
GPIO30: U1.L9(GPIO30)
GPIO32: U1.F12(GPIO32)
GPIO33: U1.L7(GPIO33)
GPIO34: U1.K7(GPIO34)
GPIO35: U1.N8(GPIO35)
GPIO36: U1.N11(GPIO36)
GPIO37: U1.M11(GPIO37)
GPIO38: U1.L11(GPIO38)
GPIO40: U1.N12(GPIO40)
GPIO41: U1.M12(GPIO41)
GPIO42: U1.C12(GPIO42)
GPIO43: U1.C11(GPIO43)
GPIO44: U1.F10(GPIO44)
GPIO45: U1.F11(GPIO45)
GPIO48_PHYCLK: U1.M13(GPIO48)
GPIO49_FSITXD0: U1.L13(GPIO49)
GPIO50_FSITXD1: U1.K9(GPIO50)
GPIO51_FSITXCLK: U1.K10(GPIO51)
GPIO52_FSIRXD0: U1.K11(GPIO52)
GPIO53_FSIRXD1: U1.K12(GPIO53)
GPIO54_FSIRXCLK: U1.K13(GPIO54)
GPIO55: U1.J13(GPIO55)
GPIO56: U1.J12(GPIO56)
GPIO57: U1.J11(GPIO57)
GPIO58: U1.J10(GPIO58)
GPIO59: U1.H13(GPIO59)
GPIO61: U1.H11(GPIO61)
GPIO62: U1.H10(GPIO62)
GPIO63: U1.G13(GPIO63)
GPIO64: U1.G12(GPIO64)
GPIO65: U1.G11(GPIO65)
GPIO66: U1.G10(GPIO66)
GPIO68: U1.B13(GPIO68)
GPIO69: U1.B12(GPIO69)
GPIO70: U1.A12(GPIO70)
GPIO71: U1.B11(GPIO71)
GPIO72: U1.A11(GPIO72)
GPIO73: U1.C10(GPIO73)
GPIO74: U1.B10(GPIO74)
GPIO75: U1.A10(GPIO75)
GPIO76: U1.E9(GPIO76)
GPIO77: U1.D9(GPIO77)
GPIO78: U1.C9(GPIO78)
GPIO79: U1.B9(GPIO79)
GPIO80: U1.E8(GPIO80)
GPIO82: U1.D8(GPIO82)
GPIO83: U1.C8(GPIO83)
GPIO84: U1.A8(GPIO84)
GPIO85: U1.A7(GPIO85)
GPIO86: U1.B7(GPIO86)
GPIO87: U1.C7(GPIO87)
GPIO88: U1.C5(GPIO88)
GPIO89: U1.D5(GPIO89)
GPIO90: U1.E5(GPIO90)
GPIO91: U1.B4(GPIO91)
GPIO92: U1.A4(GPIO92)
GPIO93: U1.A3(GPIO93)
GPIO94: U1.A2(GPIO94)
GPIO99: U1.E4(GPIO99)
GPIO103: U1.D10(GPIO103)
GPIO104: U1.A9(GPIO104)
GPIO105: U1.H12(GPIO105)
GPIO133: U1.F13(GPIO133)
MCU_TCK: U1.M10(TCK)
MCU_TDI: U1.N9(GPIO222/TDI)
MCU_TDO: U1.M9(GPIO223/TDO)
MCU_TMS: R44.1 U1.N10(TMS)
VREGENZ: R47.1 R53.2 U1.E10(VREGENZ)
X1: U1.D13(GPIO220/X1)
XRSn: C28.1 R59.1 S1.4 U1.D12(~{XRS})

Not connected (* = marked no-connect by the designer): U1 E13(GPIO221/X2)*

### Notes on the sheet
- F28P65x Device
- EPWM1A
- J8_78
- N/A
- FSITXA_D1
- CANA_TX
- CANA_RX
- EPWM1B
- EPWM2A
- EPWM2B
- J4_31
- J8_80
- J8_77
- J4_32
- J8_79
- J5_43
- FSIRXA_CLK
- FSIRXA_D1
- FSIRXA_D0
- FSITXA_CLK
- SCIB_RX
- EPWM5A
- EPWM5B
- EPWM4A
- EPWM4B
- EPWM6A
- J4_40
- J4_38
- J4_37
- J4_39
- J4_36
- J2_19
- SPIA_PTE
- ESC_LED_LINK0_ACTIVE
- ESC_LED_LINK1_ACTIVE
- ESC_LED_RUN
- ESC_TX0_ENA
- Reset Button
- J2_16
- J6_56
- LED4
- LED5
- LINA_TX
- LINA_RX
- EPWM6B
- J4_33
- J4_34
- J4_35
- J2_13
- J6_53
- ESC_MDIO_CLK
- ESC_RX1_DATA0
- ESC_RX1_DATA1
- ESC_RX1_DATA2
- ESC_RX1_DATA3
- SPIA_CLK
- SPIA_POCI
- SPIA_PICO
- EQEP1A
- ESC_TX1_DATA3
- J1_7
- J2_15
- J2_14
- J1_8
- BMP1
- ESC_PHY1_LINKSTATUS
- ESC_RX1_CLK
- ESC_RX1_DV
- ESC_RX1_ERR
- EQEP2A
- EQEP1B
- EQEP1I
- ESC_TX1_DATA0
- J2_17
- J2_12
- J6_58
- J6_51
- J8_75
- ESC_PHY_RESETn
- ESC_RX0_CLK
- ESC_TX1_DATA1
- ESC_TX1_DATA2
- EPWM8B
- Place near U1
- ESC_I2C_SCL
- ESC_MDIO_DATA
- ESC_RX0_DATA1
- ESC_RX0_DATA2
- ESC_RX0_ERR
- J5_48
- J6_57
- EQEP2B
- ESC_RX0_DATA0
- ESC_RX0_DATA3
- ESC_RX0_DV
- I2CB_SDA
- I2CB_SCL
- ESC_LED_ERR
- J8_71
- J5_50
- J8_74
- J5_49
- J2_18
- BMP2
- ESC_PHY0_LINKSTATUS
- ESC_TX0_CLK
- ESC_TX0_DATA0
- ESC_TX0_DATA1
- SCIA_TX
- SCIB_TX
- ESC_I2C_SDA
- J8_72
- J5_44/45
- J8_73
- J1_4/5
- J5_47
- J6_54
- J6_55
- SPID_PICO
- SPID_POCI
- SPID_CLK
- ESC_TX0_DATA2
- ESC_TX0_DATA3
- SCIA_RX
- FSITXA_D0
- ESC_PHY_CLK
- ESC_TX1_CLK
- ESC_TX1_ENA
- J1_3
- J1_10
- J1_9
- J6_52
- J6_59
- J8_76
- I2CA_SCL
- I2CA_SDA
- EQEP2I
- SPID_PTE
- EPWM8A
- J2_11

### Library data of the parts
C28 C55-C58 C66-C73 = CMP-0006228-2: as C1 on sheet MCU117A_Connectors
C54 C59 = CMP-0086225-1: CAP, CERM, 10 µF, 16 V,+/- 10%, X5R, 0603; Manufacturer: MuRata; SizeZ_mm: 1; SizeX_mm: 1.6; SizeArea_mm2: 1.28; VDC_V: 16V; U/M: EA; AEC Category: Q200; SizeY_mm: 0.8; Polarized: N; TaMax_C: 85°C; Value: 10uF; SizeAreaWB_mm2: 4.68; TaMin_C: -55°C
C60-C62 C64 C65 = CMP-0006825-5: CAP, CERM, 2.2 uF, 16 V, +/- 20%, X5R, 0603; Manufacturer: Wurth Elektronik; TaMin_C: -55°C; Polarized: N; SizeAreaWB_mm2: 4.68; Value1: Unknown; U/M: EA; Value: 2.2uF; TaMax_C: 85°C; SizeZ_mm: 1; SizeX_mm: 1.6; SizeY_mm: 0.8; Value2: 16V; SizeArea_mm2: 1.28; Cap_F: 2.2µF; AEC Category: Q200
L1 = CMP-0003363-1: Ferrite Bead, 220 ohm @ 100 MHz, 2 A, 0805; Manufacturer: MuRata; Imax_A: 2A; DCR_ohm: 45m; Value1: 0.045 ohm; ZTyp@100MHz_Ohm: 220; SizeArea_mm2: 2.5; SizeAreaWB_mm2: 6.75; SizeX_mm: 2; SizeY_mm: 1.25; SizeZ_mm: 1.45
L2 L3 = CMP-0003093-1: Ferrite Bead, 60 ohm @ 100 MHz, 3 A, 0805; Manufacturer: Wurth Elektronik; PartNumber: 742792063; Ztyp@1GHz_Ohm: 95.384; ZTyp@100MHz_Ohm: 60; SizeAreaWB_mm2: 6.75; DCR_ohm: 0.025; Value1: 0.025 ohm; Imax_A: 3A; SizeZ_mm: 1.45; SizeX_mm: 2; SizeY_mm: 1.25; SizeArea_mm2: 2.5
R44 R59 = CMP-0026890-5: RES, 2.2 k, 5%, 0.063 W, AEC-Q200 Grade 0, 0402; Manufacturer: Vishay-Dale; Value: 2.2k; Value_Code: 2k20; Power_W: 63mW; Value2: 0.063W; VDC_V: 50V; TempCo: 200 ppm/C; SizeArea_mm2: 0.5; SizeX_mm: 1; SizeZ_mm: 0.6; EIA_Code: E24; AEC Category: Q200; AEC Qualified: Y; AEC Grade: 0
R47 R53 = CMP-0025874-4: as R1 on sheet MCU117A_Connectors
S1 = CMP-0002328-1: Switch, SPST, 0.05 A, 12 VDC, SMD; Manufacturer: Diptronics; SizeAreaWB_mm2: 53.9; SizeArea_mm2: 27.3; SizeX_mm: 7.8; SizeY_mm: 3.5; VDC_V: 12V; PositionCount: 1; CurrentRating_mA: 50A
U1 = CMP-0097121-1: Manufacturer: Texas Instruments; Standoff Height: 0.19mm; SizeZ_mm: 1mm; AEC Qualified: No

## Sheet MCU117A_ADC.SchDoc
size 431 x 279 mm; Date: Not shown in title block; ApprovedBy: Not shown in title block; CheckedBy: Not shown in title block; Author: Not shown in title block; CompanyName: Not shown in title block; Engineer: Not shown in title block; Organization: Not shown in title block; Address1: Not shown in title block; Address2: Not shown in title block; Address3: Not shown in title block; Address4: Not shown in title block; DocumentNumber: 5; Revision: Use project parameter SCH_Rev; SheetNumber: 5; SheetTotal: 9; PageSetup: Record=PageOptions¦CenterHorizontal=True¦CenterVertical=True¦PrintScale=1.00¦XCorrection=1.00¦YCorrection=1.00¦PrintKind=0¦BorderSize=5000000¦LeftOffset=0¦BottomOffset=0¦Orientation=2¦PaperLength=1000¦PaperWidth=1000¦Scale=100¦PaperSource=15¦PrintQuality=600¦MediaType=1¦DitherType=10¦PaperKind=Letter¦PrintScaleMode=1
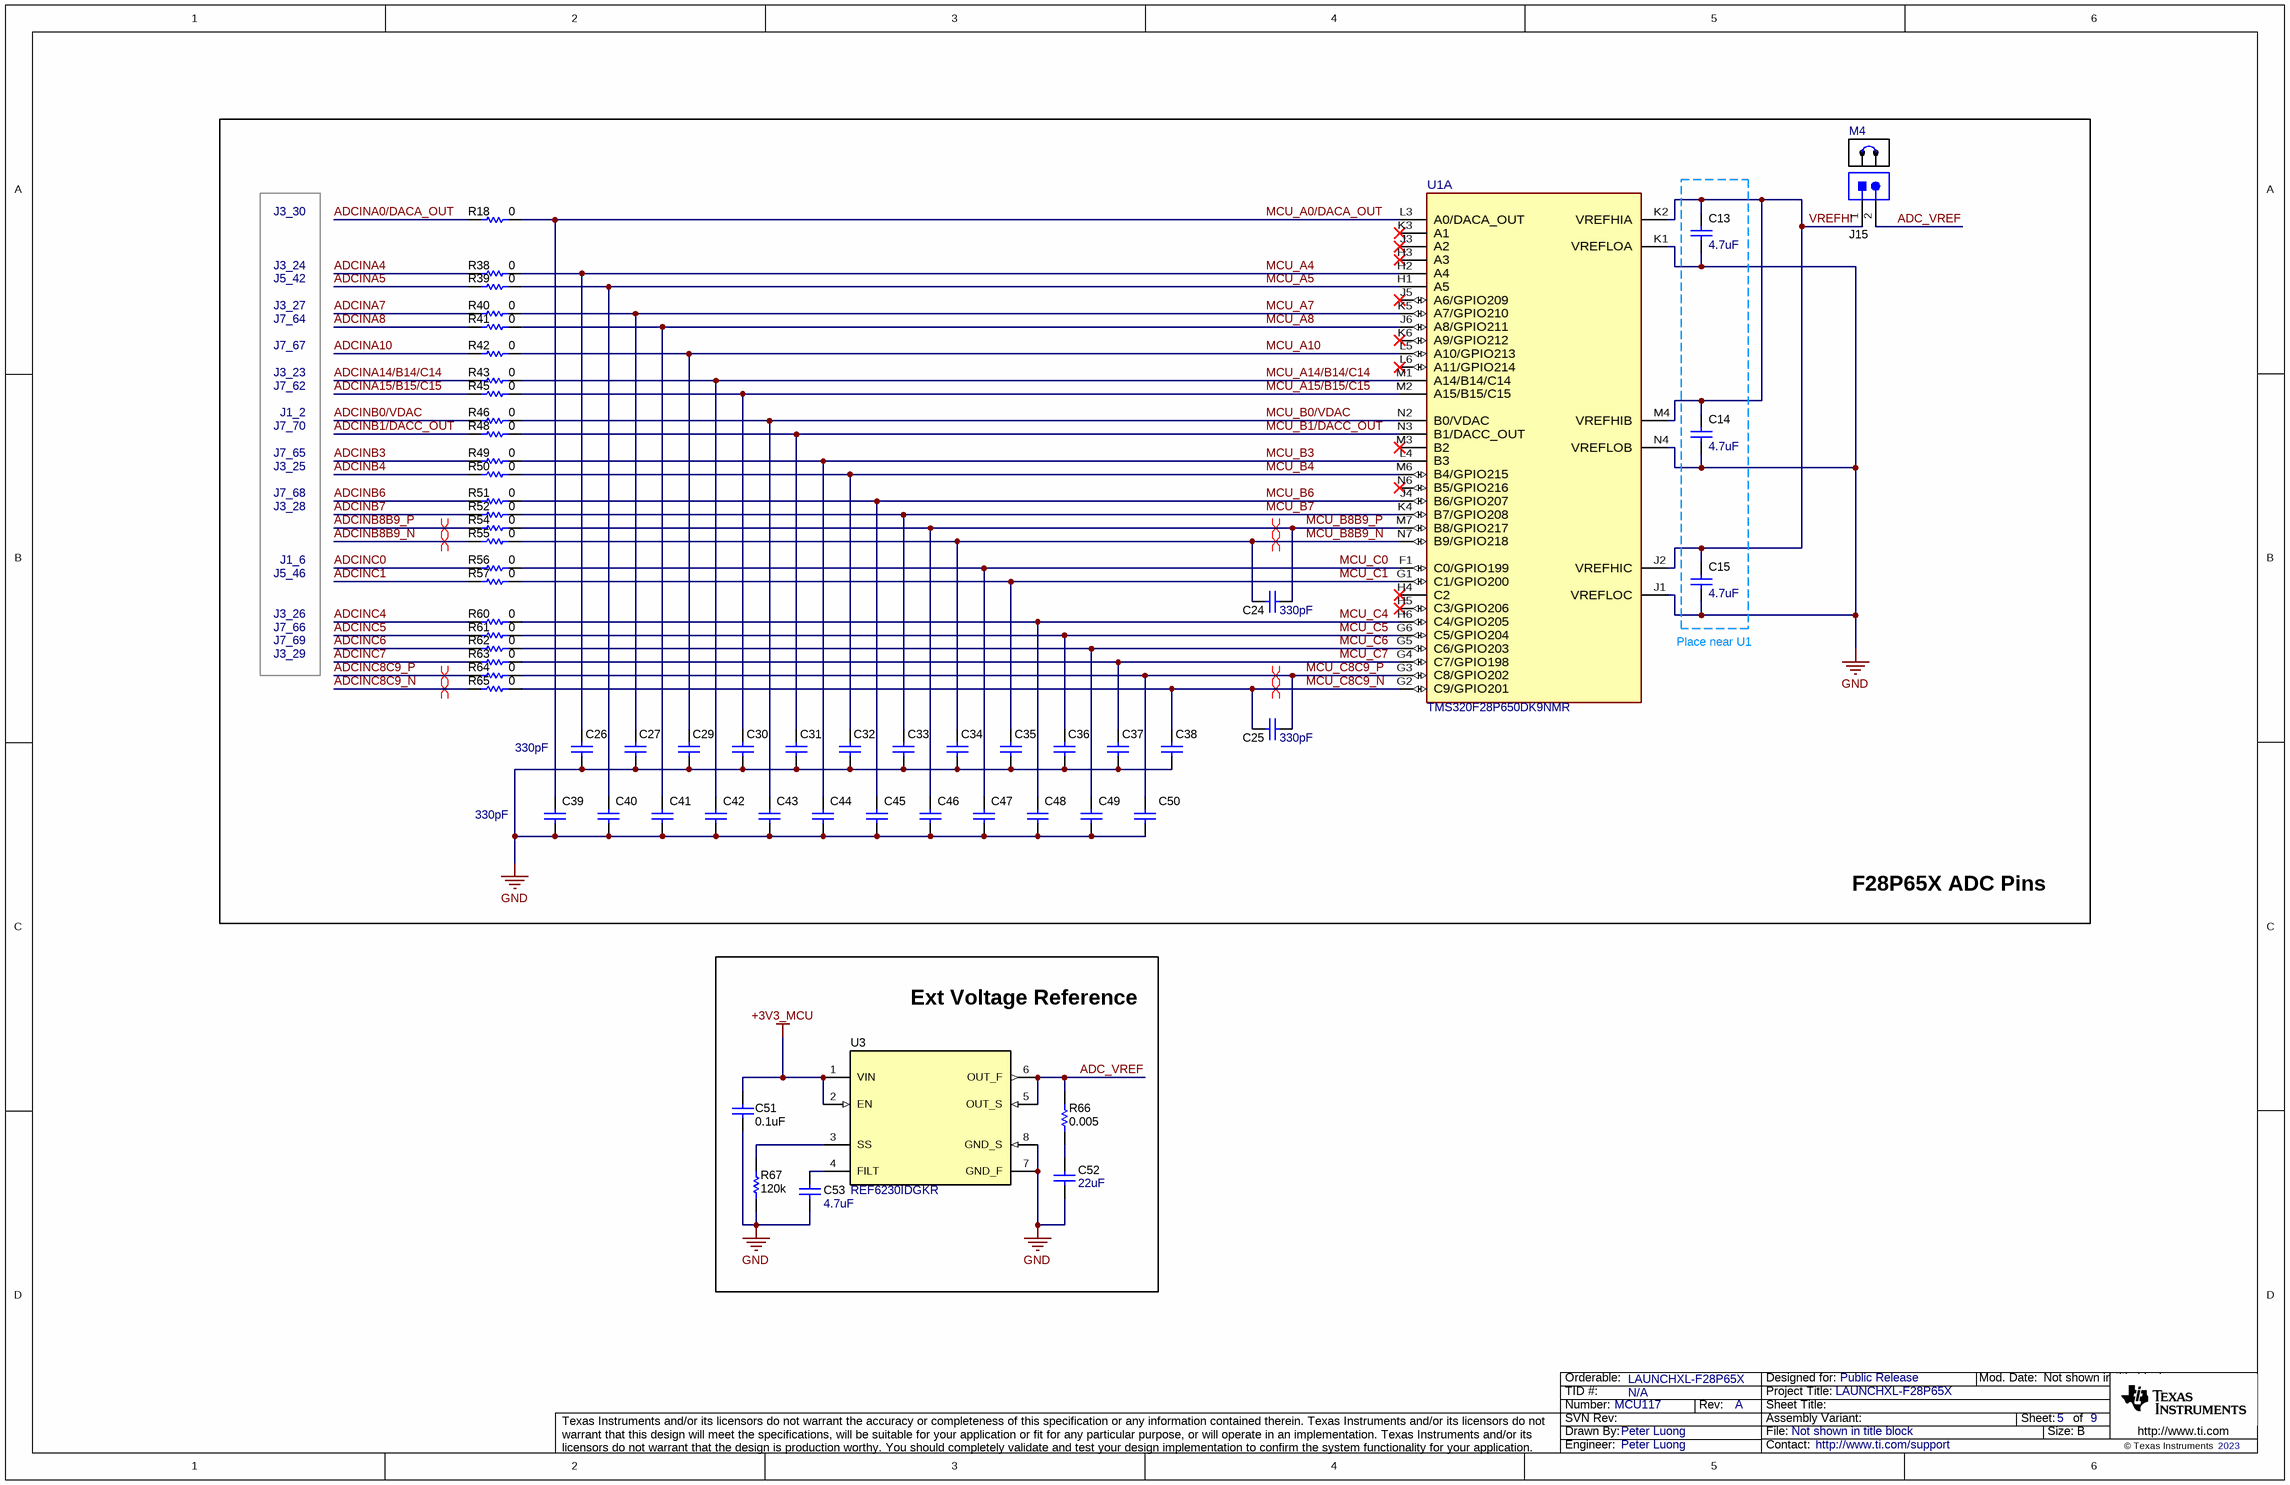
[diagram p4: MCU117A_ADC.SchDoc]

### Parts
C13  ValueDisplayed: 4.7uF  [0603]  (hidden comment: GRM188R61C475KAAJ)
C14  ValueDisplayed: 4.7uF  [0603]  (hidden comment: GRM188R61C475KAAJ)
C15  ValueDisplayed: 4.7uF  [0603]  (hidden comment: GRM188R61C475KAAJ)
C24  value 330pF  [0603]  (hidden comment: C0603C331J5GACTU)
C25  value 330pF  [0603]  (hidden comment: C0603C331J5GACTU)
C26  value 330pF  [0402]  (hidden comment: GRM1555C1H331JA01D)
C27  GRM1555C1H331JA01D  [0402]  (value not drawn)
C29  GRM1555C1H331JA01D  [0402]  (value not drawn)
C30  GRM1555C1H331JA01D  [0402]  (value not drawn)
C31  GRM1555C1H331JA01D  [0402]  (value not drawn)
C32  GRM1555C1H331JA01D  [0402]  (value not drawn)
C33  GRM1555C1H331JA01D  [0402]  (value not drawn)
C34  GRM1555C1H331JA01D  [0402]  (value not drawn)
C35  GRM1555C1H331JA01D  [0402]  (value not drawn)
C36  GRM1555C1H331JA01D  [0402]  (value not drawn)
C37  GRM1555C1H331JA01D  [0402]  (value not drawn)
C38  GRM1555C1H331JA01D  [0402]  (value not drawn)
C39  GRM1555C1H331JA01D  [0402]  (value not drawn)
C40  GRM1555C1H331JA01D  [0402]  (value not drawn)
C41  GRM1555C1H331JA01D  [0402]  (value not drawn)
C42  GRM1555C1H331JA01D  [0402]  (value not drawn)
C43  GRM1555C1H331JA01D  [0402]  (value not drawn)
C44  GRM1555C1H331JA01D  [0402]  (value not drawn)
C45  GRM1555C1H331JA01D  [0402]  (value not drawn)
C46  GRM1555C1H331JA01D  [0402]  (value not drawn)
C47  GRM1555C1H331JA01D  [0402]  (value not drawn)
C48  value 330pF  [0402]  (hidden comment: GRM1555C1H331JA01D)
C49  GRM1555C1H331JA01D  [0402]  (value not drawn)
C50  GRM1555C1H331JA01D  [0402]  (value not drawn)
C51  ValueDisplayed: 0.1uF  [0402]  (hidden comment: 885012205037)
C52  ValueDisplayed: 22uF  [0603]  (hidden comment: GRM188R61A226ME15D)
C53  ValueDisplayed: 4.7uF  [0603]  (hidden comment: GRM188R61C475KAAJ)
J15  61300211121  [WURTH_61300211121]  (value not drawn)
M4  60900213421  [Wurth_60900213421]  (value not drawn)
R18  ValueDisplayed: 0  [0402]  (hidden comment: RC0402JR-070RL)
R38  ValueDisplayed: 0  [0402]  (hidden comment: RC0402JR-070RL)
R39  ValueDisplayed: 0  [0402]  (hidden comment: RC0402JR-070RL)
R40  ValueDisplayed: 0  [0402]  (hidden comment: RC0402JR-070RL)
R41  ValueDisplayed: 0  [0402]  (hidden comment: RC0402JR-070RL)
R42  ValueDisplayed: 0  [0402]  (hidden comment: RC0402JR-070RL)
R43  ValueDisplayed: 0  [0402]  (hidden comment: RC0402JR-070RL)
R45  ValueDisplayed: 0  [0402]  (hidden comment: RC0402JR-070RL)
R46  ValueDisplayed: 0  [0402]  (hidden comment: RC0402JR-070RL)
R48  ValueDisplayed: 0  [0402]  (hidden comment: RC0402JR-070RL)
R49  ValueDisplayed: 0  [0402]  (hidden comment: RC0402JR-070RL)
R50  ValueDisplayed: 0  [0402]  (hidden comment: RC0402JR-070RL)
R51  ValueDisplayed: 0  [0402]  (hidden comment: RC0402JR-070RL)
R52  ValueDisplayed: 0  [0402]  (hidden comment: RC0402JR-070RL)
R54  ValueDisplayed: 0  [0402]  (hidden comment: RC0402JR-070RL)
R55  ValueDisplayed: 0  [0402]  (hidden comment: RC0402JR-070RL)
R56  ValueDisplayed: 0  [0402]  (hidden comment: RC0402JR-070RL)
R57  ValueDisplayed: 0  [0402]  (hidden comment: RC0402JR-070RL)
R60  ValueDisplayed: 0  [0402]  (hidden comment: RC0402JR-070RL)
R61  ValueDisplayed: 0  [0402]  (hidden comment: RC0402JR-070RL)
R62  ValueDisplayed: 0  [0402]  (hidden comment: RC0402JR-070RL)
R63  ValueDisplayed: 0  [0402]  (hidden comment: RC0402JR-070RL)
R64  ValueDisplayed: 0  [0402]  (hidden comment: RC0402JR-070RL)
R65  ValueDisplayed: 0  [0402]  (hidden comment: RC0402JR-070RL)
R66  ValueDisplayed: 0.005  [0603]  (hidden comment: ERJ3LWFR005V)
R67  ValueDisplayed: 120k  [0603]  (hidden comment: RG1608P-124-B-T5)
U1  TMS320F28P650DK9NMR  [NMR0169A-MFG]  (part A of 4)
U3  REF6230IDGKR  [DGK0008A_N]

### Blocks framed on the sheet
F28P65X ADC Pins: C13-C15 C24-C27 C29-C50 J15 M4 R18 R38-R43 R45 R46 R48-R52 R54-R57 R60-R65 U1
Ext Voltage Reference: C51-C53 R66 R67 U3

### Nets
+3V3_MCU: C51.1 U3.1(VIN) U3.2(EN)
GND: C13.2 C14.2 C15.2 C26.2 C27.2 C29.2 C30.2 C31.2 C32.2 C33.2 C34.2 C35.2 C36.2 C37.2 C38.2 C39.2 C40.2 C41.2 C42.2 C43.2 C44.2 C45.2 C46.2 C47.2 C48.2 C49.2 C50.2 C51.2 C52.2 C53.2 R67.1 U1.J1(VREFLOC) U1.K1(VREFLOA) U1.N4(VREFLOB) U3.7(GND_F) U3.8(GND_S)
ADC_VREF: J15.2 R66.2 U3.5(OUT_S) U3.6(OUT_F)
ADCINA0/DACA_OUT: R18.1
ADCINA4: R38.1
ADCINA5: R39.1
ADCINA7: R40.1
ADCINA8: R41.1
ADCINA10: R42.1
ADCINA14/B14/C14: R43.1
ADCINA15/B15/C15: R45.1
ADCINB0/VDAC: R46.1
ADCINB1/DACC_OUT: R48.1
ADCINB3: R49.1
ADCINB4: R50.1
ADCINB6: R51.1
ADCINB7: R52.1
ADCINB8B9_N: R55.1
ADCINB8B9_P: R54.1
ADCINC0: R56.1
ADCINC1: R57.1
ADCINC4: R60.1
ADCINC5: R61.1
ADCINC6: R62.1
ADCINC7: R63.1
ADCINC8C9_N: R65.1
ADCINC8C9_P: R64.1
MCU_A0/DACA_OUT: C39.1 R18.2 U1.L3(A0/DACA_OUT)
MCU_A4: C26.1 R38.2 U1.H2(A4)
MCU_A5: C40.1 R39.2 U1.H1(A5)
MCU_A7: C27.1 R40.2 U1.K5(A7/GPIO210)
MCU_A8: C41.1 R41.2 U1.J6(A8/GPIO211)
MCU_A10: C29.1 R42.2 U1.L5(A10/GPIO213)
MCU_A14/B14/C14: C42.1 R43.2 U1.M1(A14/B14/C14)
MCU_A15/B15/C15: C30.1 R45.2 U1.M2(A15/B15/C15)
MCU_B0/VDAC: C43.1 R46.2 U1.N2(B0/VDAC)
MCU_B1/DACC_OUT: C31.1 R48.2 U1.N3(B1/DACC_OUT)
MCU_B3: C44.1 R49.2 U1.L4(B3)
MCU_B4: C32.1 R50.2 U1.M6(B4/GPIO215)
MCU_B6: C45.1 R51.2 U1.J4(B6/GPIO207)
MCU_B7: C33.1 R52.2 U1.K4(B7/GPIO208)
MCU_B8B9_N: C24.1 C34.1 R55.2 U1.N7(B9/GPIO218)
MCU_B8B9_P: C24.2 C46.1 R54.2 U1.M7(B8/GPIO217)
MCU_C0: C47.1 R56.2 U1.F1(C0/GPIO199)
MCU_C1: C35.1 R57.2 U1.G1(C1/GPIO200)
MCU_C4: C48.1 R60.2 U1.H6(C4/GPIO205)
MCU_C5: C36.1 R61.2 U1.G6(C5/GPIO204)
MCU_C6: C49.1 R62.2 U1.G5(C6/GPIO203)
MCU_C7: C37.1 R63.2 U1.G4(C7/GPIO198)
MCU_C8C9_N: C25.1 C38.1 R65.2 U1.G2(C9/GPIO201)
MCU_C8C9_P: C25.2 C50.1 R64.2 U1.G3(C8/GPIO202)
VREFHI: C13.1 C14.1 C15.1 J15.1 U1.J2(VREFHIC) U1.K2(VREFHIA) U1.M4(VREFHIB)
NetC52_1: C52.1 R66.1
NetC53_1: C53.1 U3.4(FILT)
NetR67_2: R67.2 U3.3(SS)

Not connected (* = marked no-connect by the designer): U1 H3(A3)* H4(C2)* H5(C3/GPIO206)* J3(A2)* J5(A6/GPIO209)* K3(A1)* K6(A9/GPIO212)* L6(A11/GPIO214)* M3(B2)* N6(B5/GPIO216)*

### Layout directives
differential pair: ADCINB8B9_N, ADCINB8B9_P, ADCINC8C9_N, ADCINC8C9_P, MCU_B8B9_N, MCU_B8B9_P, MCU_C8C9_N, MCU_C8C9_P

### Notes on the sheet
- J3_30
- J5_42
- J3_24
- J7_67
- J7_64
- J3_27
- J7_70
- J1_2
- J7_62
- J3_23
- J7_68
- J3_25
- J7_65
- J1_6
- J3_28
- J7_66
- J3_26
- J5_46
- J3_29
- J7_69
- Place near U1

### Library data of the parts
C13-C15 C53 = CMP-0007341-4: CAP, CERM, 4.7 uF, 16 V, +/- 10%, X5R, 0603; Manufacturer: MuRata; TaMin_C: -55°C; Polarized: N; SizeAreaWB_mm2: 4.68; Value1: Unknown; U/M: EA; Value: 4.7uF; TaMax_C: 85°C; SizeZ_mm: 1; SizeX_mm: 1.6; SizeY_mm: 0.8; Value2: 16V; SizeArea_mm2: 1.28; Cap_F: 4.7µF; AEC Category: Q200
C24 C25 = CMP-0006920-4: CAP, CERM, 330 pF, 50 V, +/- 5%, C0G/NP0, 0603; Manufacturer: Kemet; TaMin_C: -55°C; Polarized: N; SizeAreaWB_mm2: 4.68; Value1: Unknown; U/M: EA; TaMax_C: 125°C; SizeZ_mm: 1; SizeX_mm: 1.6; SizeY_mm: 0.8; Value2: 50V; SizeArea_mm2: 1.28; AEC Category: Q200
C26 C48 = CMP-0006456-2: CAP, CERM, 330 pF, 50 V, +/- 5%, C0G/NP0, 0402; Manufacturer: MuRata; TaMin_C: -55°C; Polarized: N; SizeAreaWB_mm2: 3; Value1: Unknown; U/M: EA; TaMax_C: 125°C; SizeZ_mm: 0.6; SizeX_mm: 1; SizeY_mm: 0.5; Value2: 50V; AEC Category: Q200
C27 C29-C47 C49 C50 = CMP-0006456-2: CAP, CERM, 330 pF, 50 V, +/- 5%, C0G/NP0, 0402; Manufacturer: MuRata; TaMin_C: -55°C; Polarized: N; SizeAreaWB_mm2: 3; Value1: Unknown; U/M: EA; Value: 330pF; TaMax_C: 125°C; SizeZ_mm: 0.6; SizeX_mm: 1; SizeY_mm: 0.5; Value2: 50V; AEC Category: Q200
C51 = CMP-0006228-2: as C1 on sheet MCU117A_Connectors
C52 = CMP-0007324-5: CAP, CERM, 22 uF, 10 V, +/- 20%, X5R, 0603; Manufacturer: MuRata; TaMin_C: -55°C; Polarized: N; SizeAreaWB_mm2: 4.68; Value1: Unknown; U/M: EA; Value: 22uF; TaMax_C: 85°C; SizeZ_mm: 1; SizeX_mm: 1.6; SizeY_mm: 0.8; Value2: 10V; SizeArea_mm2: 1.28; Cap_F: 22µF; AEC Category: Q200
J15 = CMP-0054794-1: as JP9 on sheet MCU117A_Connectors
M4 = CMP-0003761-2: as M1 on sheet MCU117A_Connectors
R18 R38-R43 R45 R46 R48-R52 R54-R57 R60-R65 = CMP-0027004-2: RES, 0, 5%, 0.063 W, 0402; Manufacturer: Yageo America; Power_W: 63mW; TempCo: 200 ppm/C; Value_Code: 0000; U/M: EA; Value: 0; EIA_Code: E24; SizeX_mm: 1; SizeY_mm: 0.5; SizeZ_mm: 0.6; Value2: 0.063W; VDC_V: 50V; AEC Category: Q200
R66 = CMP-0022710-2: RES, 0.005, 1%, 0.25 W, AEC-Q200 Grade 1, 0603; Manufacturer: Panasonic; Power_W: 250mW; TempCo: ppm/C; Value_Code: 5L000; U/M: EA; Value: 0.005; EIA_Code: E96; Res_ohm: 5m; SizeX_mm: 1.6; SizeY_mm: 0.8; SizeZ_mm: 1; Value2: 0.25W; SizeArea_mm2: 1.28; AEC Qualified: Y; AEC Category: Q200
R67 = CMP-0023427-3: RES, 120 k, 0.1%, 0.1 W, 0603; Manufacturer: Susumu Co Ltd; Power_W: 100mW; TempCo: 25 ppm/C; U/M: EA; Value: 120k; EIA_Code: E192; SizeX_mm: 1.6; SizeY_mm: 0.8; SizeZ_mm: 1; Value2: 0.1W; SizeArea_mm2: 1.28; VDC_V: 75V; AEC Category: Q200
U1 = CMP-0097121-1: as U1 on sheet MCU117A_F28P65X_Device
U3 = CMP-0077709-1: High-Precision Voltage Reference with Integrated High-Bandwidth Buffer, DGK0008A (VSSOP-8); Alternate PartNumber: REF6230IDGKT; Alternate Manufacturer: Texas Instruments; SizeAreaWB_mm2: 35.955; SizeZ_mm: 1.1; SizeX_mm: 5.05; SizeY_mm: 3.1; SizeArea_mm2: 15.655; CompType: IC; AEC Qualified: N; AEC Category: Q200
